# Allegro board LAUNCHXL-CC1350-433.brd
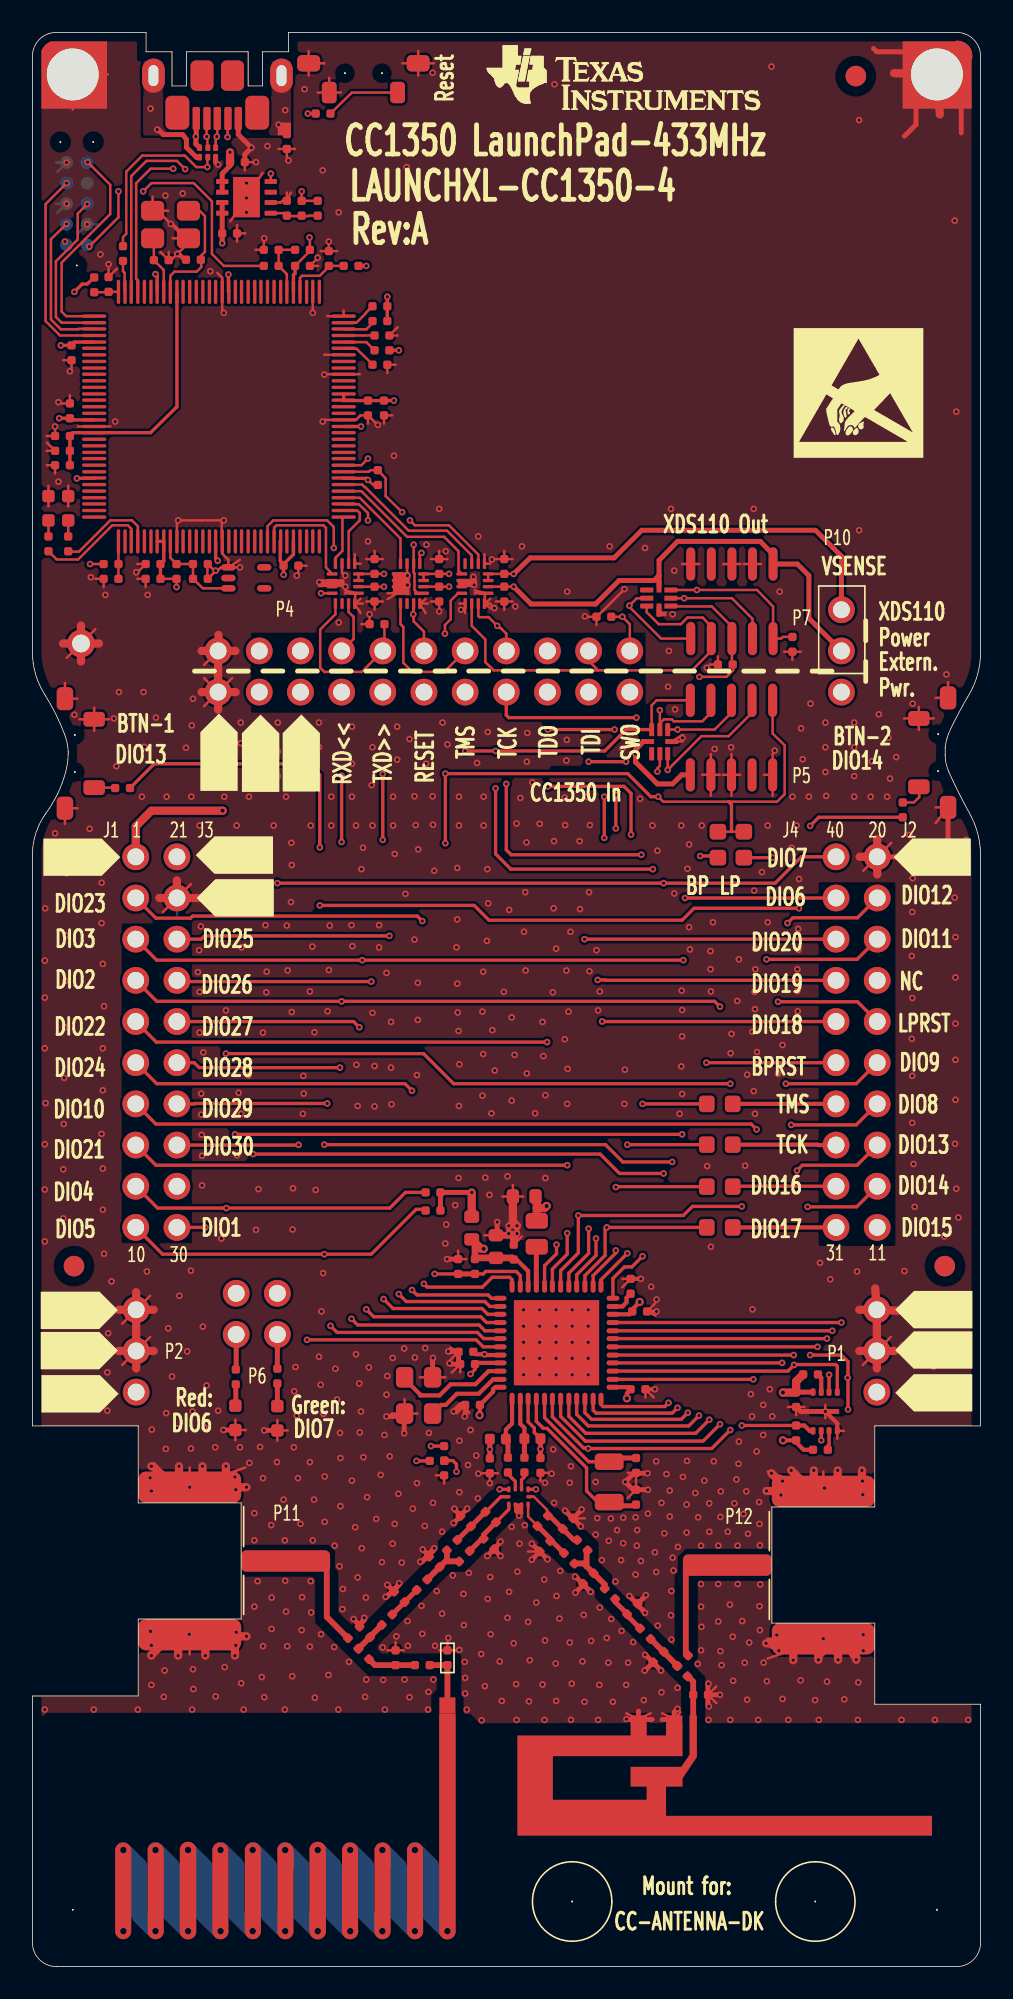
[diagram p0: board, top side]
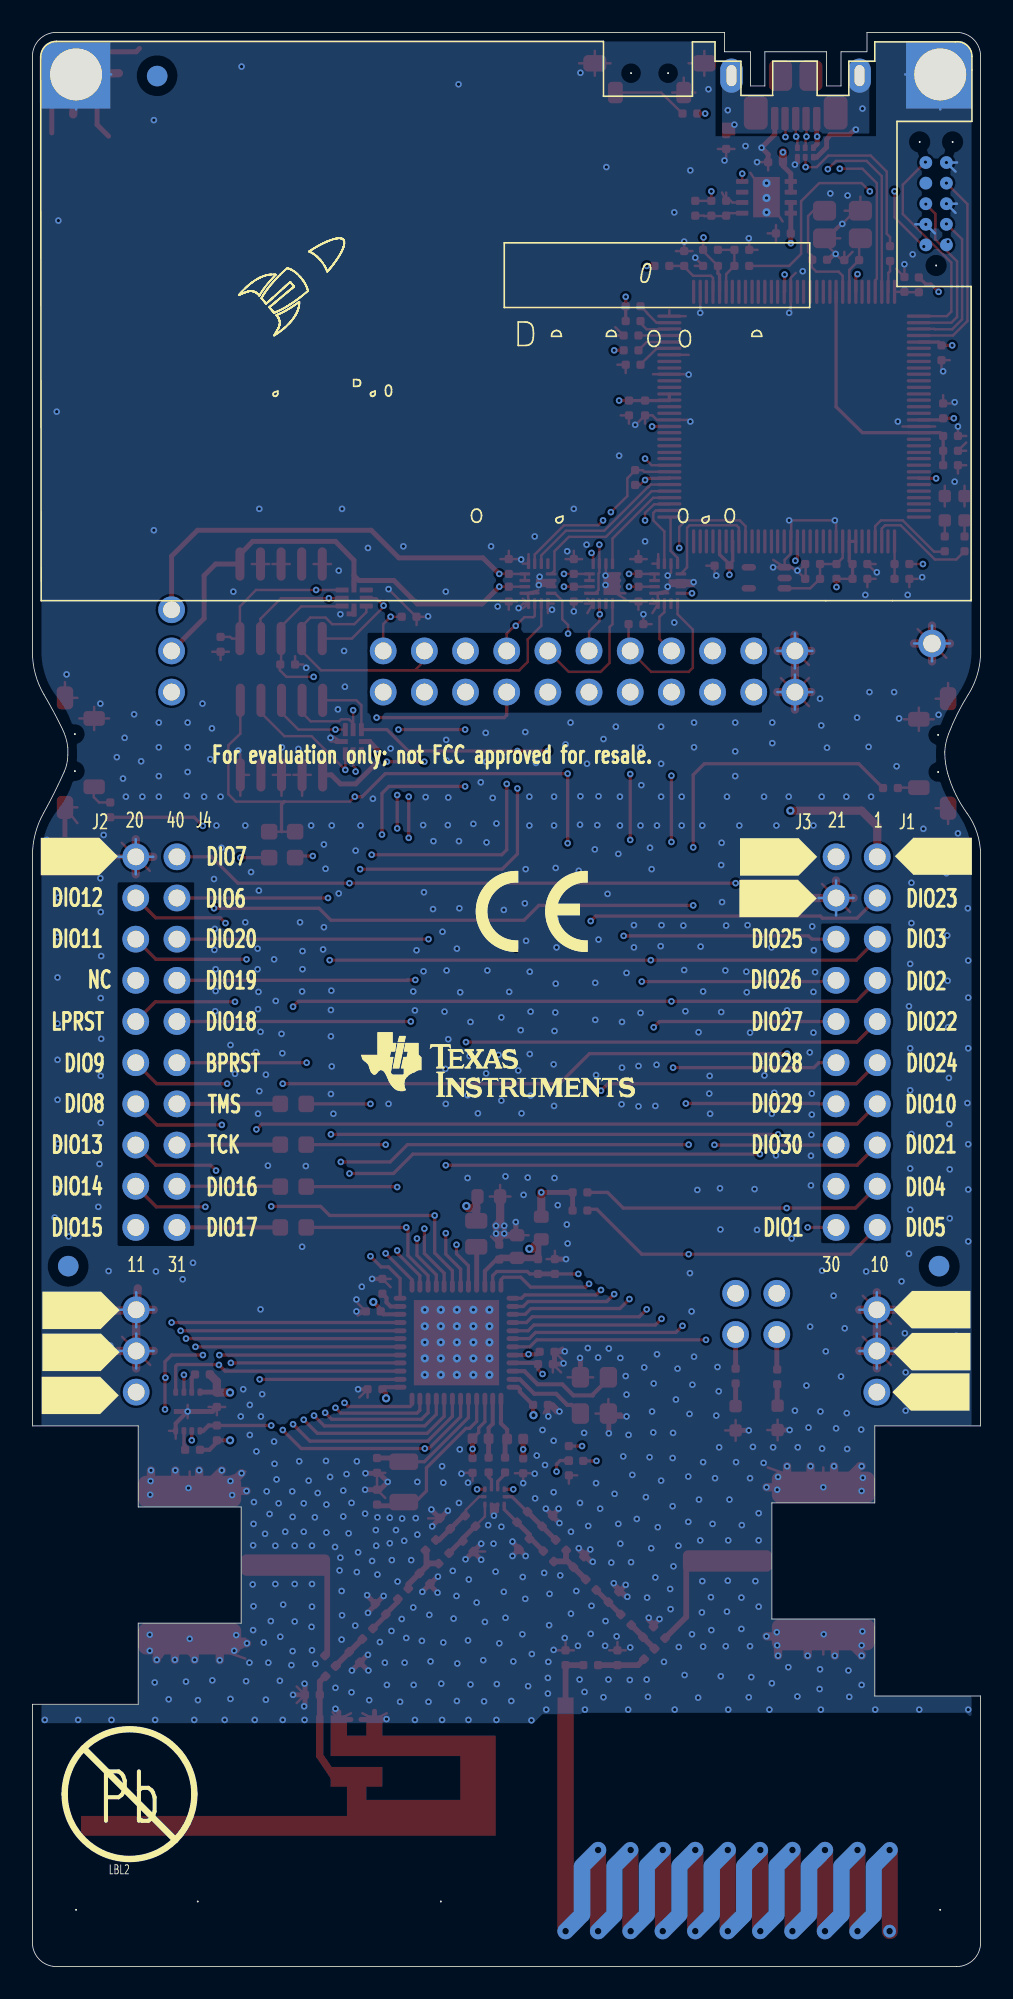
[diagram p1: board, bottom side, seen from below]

Outline 58.5 x 119.3 mm; copper layers: TOP, L2, L3, BOTTOM. Coordinates in mm from the lower left corner of the outline.
Outline path: 0,117.86 0,81.1 arc(0.19,79.73) 0.76,78.46 arc(1.43,77.27) 1.98,76.02 arc(2.14,75.49) 2.21,74.93 2.21,74.85 arc(2.16,74.23) 2.03,73.61 arc(1.55,72.32) 0.84,71.15 arc(0.21,69.92) 0,68.55 0,33.35 6.53,33.35 6.53,28.6 12.88,28.6 12.88,21.44 6.53,21.44 6.53,16.69 0,16.69 0,1.47 arc(0.43,0.43) 1.47,0 57.05,0 arc(58.07,0.44) 58.5,1.47 58.5,16.18 51.97,16.18 51.97,21.18 45.62,21.18 45.62,28.35 51.97,28.35 51.97,33.35 58.5,33.35 58.5,68.5 arc(58.32,69.87) 57.81,71.15 arc(57.15,72.4) 56.54,73.69 arc(56.37,74.19) 56.31,74.73 56.31,75.18 arc(56.43,75.77) 56.64,76.33 arc(57.19,77.41) 57.79,78.46 arc(58.32,79.73) 58.5,81.1 58.5,117.83 arc(58.06,118.87) 57.02,119.3 15.8,119.3 15.8,118.11 14.2,118.11 14.2,116 13.31,116 13.31,118.11 9.5,118.11 9.5,116 8.61,116 8.61,118.11 7.01,118.11 7.01,119.3 1.47,119.3 arc(0.44,118.88) 0,117.86

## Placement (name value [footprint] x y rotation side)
A1  Antenna PCB helix 868/915MHz  [ANTENNA868_915MHZ_A2N]  25.6 16.1 180 top
A2  2.4GHz  [ANTENNA_DN007AN]  40.77 15.24 180 top
C3  100nF  [CAPC1005X60B2N]  36.91 35.61 0 top
C4  100nF  [CAPC1005X60B2N]  37.01 40.41 0 top
C5  100nF  [CAPC1005X60B2N]  27.2 37.92 180 top
C6  22uF  [CAPC1608X100A2L]  28.6 43.71 90 top
C7  100nF  [CAPC1005X60B2N]  29.69 43.61 90 top
C8  22uF  [CAPC1608X100A2L]  31.04 47.5 180 top
C9  100nF  [CAPC1005X60B2N]  27.61 34.65 180 top
C11  8.2pF  [CAPC1005X60B2N]  27.05 27.15 135 top
C12  4.7pF  [CAPC1005X60B2N]  25.12 24.64 135 top
C13  12pF  [CAPC1005X60B2N]  22.96 22.48 135 top
C14  4.7pF  [CAPC1005X60B2N]  20.83 20.32 135 top
C15  330pF  [CAPC1005X60B2N]  20.12 19.61 315 top
C16  100nF  [CAPC1005X60B2N]  27.31 37.16 180 top
C17  12pF  [CAPC1005X60B2N]  37.24 28.5 90 top
C18  12pF  [CAPC1005X60B2N]  37.24 31.37 270 top
C19  1uF  [CAPC1005X60B2N]  36.91 41.5 90 top
C20  100nF  [CAPC1005X60B2N]  26.26 42.72 90 top
C21  1pF  [CAPC1005X60B2N]  31.29 25.6 45 top
C22  8.2pF  [CAPC1005X60B2N]  26.97 25.63 225 top
C24  1.5pF  [CAPC1005X60B2N]  40.41 17.91 135 top
C30  100nF  [CAPC1005X60B2N]  47.12 35.43 270 top
C32  100nF  [CAPC1005X60B2N]  9.91 86.51 0 top
C33  12pF  [CAPC1005X60B2N]  10.39 105.28 180 top
C34  12pF  [CAPC1005X60B2N]  7.49 105.26 0 top
C35  10nF  [CAPC1005X60B2N]  15.49 86.41 0 top
C36  10nF  [CAPC1005X60B2N]  2.31 95.5 90 top
C37  10nF  [CAPC1005X60B2N]  2.41 100 270 top
C38  100nF  [CAPC1005X60B2N]  16.21 104.9 0 top
C39  100nF  [CAPC1005X60B2N]  20.7 96.6 270 top
C40  1uF  [CAPC1005X60B2N]  21.69 96.6 270 top
C41  10nF  [CAPC1005X60B2N]  7.9 86.51 180 top
C42  1uF  [CAPC1005X60B2N]  7.9 85.6 180 top
C43  100nF  [CAPC1005X60B2N]  2.31 94.41 180 top
C44  1uF  [CAPC1005X60B2N]  2.31 93.5 180 top
C45  2.2uF  [CAPC1005X60B2N]  2.31 92.61 180 top
C46  100nF  [CAPC1005X60B2N]  18.29 104.9 90 top
C47  15pF  [CAPC1005X60B2N]  16.61 108.92 270 top
C48  2.2uF  [CAPC1005X60B2N]  12.19 111.3 0 top
C49  2.2uF  [CAPC1005X60B2N]  11.71 106.91 0 top
C50  10nF  [CAPC1005X60B2N]  9.91 85.6 0 top
C52  100nF  [CAPC1005X60B2N]  21.11 85.9 90 top
C53  100nF  [CAPC1005X60B2N]  21.11 85.12 270 top
C54  100nF  [CAPC1005X60B2N]  25.1 85.9 90 top
C55  100nF  [CAPC1005X60B2N]  25.1 85.12 270 top
C56  100nF  [CAPC1005X60B2N]  29.11 85.9 90 top
C57  100nF  [CAPC1005X60B2N]  29.11 85.12 270 top
C58  100pF  [CAPC1005X60B2N]  31.34 31.37 270 top
C59  DNM  [CAPC1005X60B2N]  40.77 16.76 0 top
C60  1pF  [CAPC1005X60B2N]  33.6 26.31 315 top
C61  DNM_0402  [CAPC1005X60B2N]  34.62 24.26 225 top
C62  3.6pF  [CAPC1005X60B2N]  37.34 22.38 225 top
C63  12pF  [CAPC1005X60B2N]  29.34 31.39 270 top
C64  12pF  [CAPC1005X60B2N]  30.35 31.39 270 top
C65  100pF  [CAPC1005X60B2N]  28.22 31.34 270 top
C67  DNM_0402  [CAPC1005X60B2N]  39.8 18.54 45 top
C68  1pF  [CAPC1005X60B2N]  38.3 18.77 45 top
C69  DNM_0402  [CAPC1005X60B2N]  20.12 19.61 135 top
C70  100nF  [CAPC1005X60B2N]  4.7 103.3 90 top
C71  1.8pF  [CAPC1005X60B2N]  23.6 18.59 0 top
CR1  LPL296-J2L2-25  [LEDC1707X65L]  15.11 33.07 90 top
CR2  LS L296-P2Q2-1  [LEDC1708X67L]  12.52 33.1 90 top
CR4  LS L296-P2Q2-1  [LEDC1708X67L]  0.99 90.7 270 top
CR5  LPL296-J2L2-25  [LEDC1707X65L]  2.21 90.7 270 top
CR6  TPD4E004DRY  [SON50P100X145X60-6N]  10.31 111.61 0 top
CR7  TPD6E004RSER  [QFN50P150X150X60-8N]  37.9 84.91 270 top
CR8  TPD6E004RSER  [QFN50P150X150X60-8N]  38.2 74.8 0 top
FIDU1  FIDU_1.27mm  [FID127X142]  50.8 116.61 0 top
FIDU2  FIDU_1.27mm  [FID127X142]  2.57 43.21 0 top
FIDU3  FIDU_1.27mm  [FID127X142]  56.29 43.21 0 top
FIDU4  FIDU_1.27mm  [FID127X142]  50.8 116.61 180 bottom
FIDU5  FIDU_1.27mm  [FID127X142]  2.57 43.21 180 bottom
FIDU6  FIDU_1.27mm  [FID127X142]  56.29 43.21 180 bottom
FL1  BLM18HE152SN1  [FIL_BLM18HE152SN1DL]  27.1 44.86 90 top
J1  SSQ-110-23-L-D  [SAMTEC_SSQ11023LD_A2B]  6.38 68.45 0 bottom
J2  SSQ-110-23-L-D  [SAMTEC_SSQ11023LD_A2B]  49.58 68.45 0 bottom
J6  105164-0001  [MOLEX_1051640001_A2N]  10.11 114 0 top
L1  6.8uH  [INDC2012X150L]  31.12 44.4 90 top
L11  2.2nH  [INDC1005X60B2N]  32.72 27 45 top
L12  15nH  [INDC1005X60B2N]  26.21 26.31 225 top
L13  20nH  [INDC1005X60B2N]  24.36 23.88 225 top
L14  20nH  [INDC1005X60B2N]  22.2 21.72 225 top
L21  2.2nH  [INDC1005X60B2N]  32.79 25.5 315 top
L25  1.5nH  [INDC1005X60B2N]  35.31 23.32 315 top
L26  2.2nH  [INDC1005X60B2N]  37.49 20.85 315 top
L27  15nH  [INDC1005X60B2N]  27.84 26.39 315 top
L28  100nH  [IND_LQW15AN]  29.21 32.54 180 top
L29  100nH  [IND_LQW15AN]  30.35 32.56 0 top
L30  33nH  [INDC1005X60B2N]  28.6 27.41 135 top
L31  DNM  [INDC1005X60B2N]  31.8 27.81 225 top
L32  DNM  [INDC1005X60B2N]  22.4 18.59 90 top
L33  33nH  [INDC1005X60B2N]  25.6 18.59 90 top
LBL2  NON_COMPONENT_LABEL_8mm  [LABEL_PB-FREE_8MM_A2N]  56.72 6.43 180 bottom
LBL4  CE_label  [CE_LABEL]  28.52 62.59 180 bottom
M1  SNT-100-BK-G  [SAMTEC_SNT100BKG]  12.7 77.39 90 top
M2  SNT-100-BK-G  [SAMTEC_SNT100BKG]  15.29 77.39 90 top
M3  SNT-100-BK-G  [SAMTEC_SNT100BKG]  17.81 77.39 90 top
M4  SNT-100-BK-G  [SAMTEC_SNT100BKG]  20.29 77.39 90 top
M5  SNT-100-BK-G  [SAMTEC_SNT100BKG]  22.91 77.39 90 top
M6  SNT-100-BK-G  [SAMTEC_SNT100BKG]  25.4 77.39 90 top
M7  SNT-100-BK-G  [SAMTEC_SNT100BKG]  27.99 77.39 90 top
M8  SNT-100-BK-G  [SAMTEC_SNT100BKG]  30.51 77.39 90 top
M9  SNT-100-BK-G  [SAMTEC_SNT100BKG]  33.1 77.39 90 top
M10  SNT-100-BK-G  [SAMTEC_SNT100BKG]  35.61 77.39 90 top
M11  SNT-100-BK-G  [SAMTEC_SNT100BKG]  38.1 77.39 90 top
M12  SNT-100-BK-G  [SAMTEC_SNT100BKG]  51.21 79.91 90 top
M13  SNT-100-BK-G  [SAMTEC_SNT100BKG]  13.77 37.69 90 top
M14  SNT-100-BK-G  [SAMTEC_SNT100BKG]  16.38 37.69 90 top
MH1  HOLE_3.2mm_NPL  [MTG320]  2.49 3.51 0 top
MH2  HOLE_3.2mm_NPL  [MTG320]  55.8 3.51 0 top
MH3  HOLE_3.2mm_PTH  [MTG320_380]  2.49 116.71 0 top
MH4  HOLE_3.2mm_PTH  [MTG320_380]  55.8 116.71 0 top
MH5  HOLE_1.1mm_PTH  [MTG110_170]  3 81.61 0 top
NOREF  -  []  8.41 66.01 0 top
NOREF#2  -  []  0.61 67.21 0 top
NOREF#3  -  []  51.51 38.1 0 top
NOREF#4  -  []  0 117.65 0 top
NOREF#5  -  []  53.81 0 90 top
NOREF#6  -  []  51.51 35.61 0 top
NOREF#7  #VALUE  [unnamed#2]  33.3 4.01 0 top
NOREF#8  -  []  1.47 0 90 top
NOREF#9  -  []  13.89 70.21 90 top
NOREF#10  -  []  55.6 0 90 top
NOREF#11  -  []  51.41 66.01 0 top
NOREF#12  -  []  0 1.75 0 top
NOREF#13  -  []  8.41 63.5 0 top
NOREF#14  -  []  56.54 0 90 top
NOREF#15  -  []  1.47 0 90 top
NOREF#16  -  []  53.01 34.01 0 top
NOREF#17  #VALUE  []  46.96 93.07 0 top
NOREF#18  -  []  -1.9 32.79 0 top
NOREF#19  -  []  17.81 72.42 90 top
NOREF#20  -  []  78.99 112.19 0 top
NOREF#21  -  []  16.61 70 90 top
NOREF#22  -  []  -1.8 35.61 0 top
NOREF#23  -  []  -1.8 38.1 0 top
NOREF#24  -  []  0 117.86 0 top
NOREF#25  -  []  7.11 38.1 180 bottom
NOREF#26  -  []  57.99 34.01 180 bottom
NOREF#27  -  []  60.2 35.51 180 bottom
NOREF#28  -  []  17.2 63.5 180 bottom
NOREF#29  -  []  60.3 66.09 180 bottom
NOREF#30  -  []  17.3 65.91 180 bottom
NOREF#31  -  []  60.2 38.1 180 bottom
NOREF#32  -  []  7.11 35.51 180 bottom
NOREF#33  -  []  51.54 89.54 180 bottom
NOREF#34  -  []  5.51 67.11 180 bottom
NOREF#35  -  []  7.11 32.89 180 bottom
P1  BB02-HC031-KB1-603000  [GRADCONN_BB02HC031KB1603000_A2B]  52.1 35.43 90 top
P2  BB02-HC031-KB1-603000  [GRADCONN_BB02HC031KB1603000_A2B]  6.4 35.43 90 top
P4  BB02-HJ221-KB1-603000  [GRADCONN_BB02HJ221KB160300_A2B]  36.86 81.15 180 top
P5  FTSH-105-01-F-DV-K  [SAMTEC_FTSH-105-01-F-DV-K-10L]  40.59 73.51 0 top
P6  BB02-HJ041-KB1-603000  [GRADCONN_BB02HJ041KB1603000_A2B]  12.57 38.99 0 top
P7  FTSH-105-01-F-DV-K  [SAMTEC_FTSH-105-01-F-DV-K-10L]  45.69 86.51 180 top
P8  TC2050-IDC-NL  [TAGCONNECT_TC2050IDCNLN]  2.11 106.2 90 bottom
P10  BB02-HC031-KB1-603000  [GRADCONN_BB02HC031KB1603000_A2B]  49.91 83.69 270 top
P11  142-0721-88  [CINCH_1420721882_A2N]  15.62 25.02 180 top
P12  142-0721-88  [CINCH_1420721882_A2N]  42.88 24.76 0 top
R1  100k  [RESC1005X40B2N]  27.31 42.72 90 top
R2  3.3k  [RESC1005X40B2N]  24.26 47.75 0 top
R3  3.3k  [RESC1005X40B2N]  24.26 46.63 0 top
R11  2.2k  [RESC1005X40B2N]  47.12 33.38 270 top
R14  220  [RESC1005X40B2N]  12.55 35.92 90 top
R15  180  [RESC1005X40B2N]  15.11 35.97 90 top
R17  10k  [RESC1005X40B2N]  16.21 105.89 0 top
R18  4.7k  [RESC1005X40B2N]  8.89 86.51 270 top
R19  DNM  [RESC1005X40B2N]  5.59 105.21 90 top
R20  100  [RESC1005X40B2N]  15.19 104.9 180 top
R21  DNM  [RESC1005X40B2N]  15.19 105.89 180 top
R22  330k  [RESC1005X40B2N]  5.31 86.51 180 top
R23  180  [RESC1005X40B2N]  0.99 88.21 270 top
R24  220k  [RESC1005X40B2N]  5.31 85.6 180 top
R25  220  [RESC1005X40B2N]  2.21 88.21 270 top
R27  1k  [RESC1005X40B2N]  21.89 101.5 180 top
R28  4.87k  [RESC1005X40B2N]  21.89 98.81 180 top
R29  1k  [RESC1005X40B2N]  21.11 100.61 0 top
R30  1k  [RESC1005X40B2N]  21.11 99.69 0 top
R31  51  [RESC1005X40B2N]  19.2 104.9 0 top
R32  33k  [RESC1005X40B2N]  15.7 112.12 90 top
R33  51k  [RESC1005X40B2N]  17.6 108 90 top
R34  30k  [RESC1005X40B2N]  15.7 108.92 270 top
R39  1k  [RESC1005X40B2N]  21.89 102.41 180 top
R46  DNM  [RESC1608X55N]  43.21 53.21 180 top
R47  DNM  [RESC1608X55N]  43.21 50.7 180 top
R48  DNM  [RESC1608X55N]  43.21 48.11 180 top
R49  DNM  [RESC1608X55N]  43.21 45.59 180 top
R51  DNM  [RESC1608X55N]  43.89 68.4 90 top
R52  0  [RESC1608X55N]  42.29 70 270 top
R55  100  [RESC1005X40B2N]  53.7 71.81 270 top
R56  100  [RESC1005X40B2N]  5.11 72.69 0 top
R57  100  [RESC1005X40B2N]  18.39 114.3 180 top
R58  3.3k  [RESC1005X40B2N]  21.31 92.3 270 top
R59  DNM  [RESC1005X40B2N]  49.07 31.88 180 top
R60  DNM  [RESC1005X40B2N]  48.46 36.53 180 top
R61  100k  [RESC1005X40B2N]  20.8 82.8 0 top
R62  100k  [RESC1005X40B2N]  34.8 83.26 0 top
R63  100k  [RESC1005X40B2N]  42.29 80.31 0 top
R65  100k  [RESC1005X40B2N]  46.89 81.1 90 top
R66  100  [RESC1005X40B2N]  3.81 104.19 270 top
R67  DNM  [RESC1005X40B2N]  24.51 31.19 0 top
R68  DNM  [RESC1005X40B2N]  25.4 30.3 90 top
R69  0  [RESC1005X40B2N]  25.4 31.19 90 top
SW1  1188E-1K2-V  [SW_1188E1K2V_A2N]  2.01 78.21 270 top
SW2  1188E-1K2-V  [SW_1188E1K2V_A2N]  56.49 71.5 90 top
SW3  1188E-1K2-V  [SW_1188E1K2V_A2N]  23.8 117.4 180 top
U1  CC1350F128RGZ  [QFNFC50P700X700X80-49CN]  29.59 35 0 top
U4  MX25R8035FZUIL0  [SON50P300X200X60-9B2L]  48.16 33.05 0 top
U5  TM4C1294NCPDTT3R  [QFP40P1600X1600X120-128N]  5.31 87.91 0 top
U6  LM4040B25IDCK  [SOT65P210X110-5N]  12.09 86.31 270 top
U7  TPS79601DR  [SON65P300X300X100-9AL]  11.71 110.11 270 top
U8  SN74AVC4T245RSV  [QFNFC40P180X260X55-16A2L]  19.99 84.71 90 top
U9  SN74AVC4T245RSV  [QFNFC40P180X260X55-16A2L]  27.99 84.71 90 top
U10  SN74AVC4T245RSV  [QFNFC40P180X260X55-16A2L]  24 84.71 90 top
U11  XMSSJE3G0PA-003  [SW_XMSSJE3G0PA003_A2N]  29.39 28.5 0 top
UNK#REFDES  -  []  29.01 118.52 0 top
UNK#REFDES#2  -  []  37.21 57.63 180 bottom
Y1  32.768kHz  [XTAL_FC-135N]  35.59 28.65 90 top
Y2  24MHz  [OSCCC250X320X60-4L]  24.69 34.11 90 top
Y3  16MHz  [OSCCC250X320X100-4BN]  9.63 108.31 180 top

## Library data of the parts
A1 = ANTENNA_0: User Part Number: #PN
A2 = ANTENNA_DN007_0
C3-C5 C7 C9 C11-C22 C24 C30 C32-C50 C52-C65 C67-C71 = CAPACITOR: User Part Number: #PN
C6 C8 = CAPACITOR: User Part Number: #PN; alternate symbols: (CAPC1608X100A2L,CAPC1608X100A2M)
CR1 CR5 = LED: alternate symbols: (LEDC1707X65L,LEDC1707X65M)
CR2 CR4 = LED: alternate symbols: (LEDC1708X67L,LEDC1708X67M)
CR6 = DIODE_TPD4E004_SON6: User Part Number: #PN; alternate symbols: (SON50P100X145X65-6L,SON50P100X145X65-6M)
CR7 CR8 = DIODE_TVS_TPD6E004_QFN8: alternate symbols: (QFN50P150X150X60-8L,QFN50P150X150X60-8M)
FIDU1-FIDU6 = FIDMARK
FL1 = FILTER_0: alternate symbols: (FIL_BLM18HE152SN1DL,FIL_BLM18HE152SN1DM)
J1 J2 = CONN_HEADER_2X10_J_S_V1: User Part Number: #PN; alternate symbols: (SAMTEC_SSQ11023LD_A2C,SAMTEC_SSQ11023LD_A2A)
J6 = CONN_USB_MICRO_B_2MH: User Part Number: #PN; alternate symbols: (MOLEX_1051640001_A2L,MOLEX_1051640001_A2M)
L1 = INDUCTOR_0: alternate symbols: (INDC2012X150L,INDC2012X150M)
L11-L14 L21 L25-L27 L30-L32 = INDUCTOR_0: User Part Number: #PN
L28 L29 = INDUCTOR_0: alternate symbols: (IND_LQW15AM,IND_LQW15AL)
L33 = INDUCTOR: User Part Number: #PN
LBL2 = LABEL_Pb-free_V1: User Part Number: #PN
LBL4 = CE_LABEL
M1-M14 = MECH_SHUNT_JUMPER_V1: User Part Number: #PN
MH1 MH2 = HOLE_NPL
MH3-MH5 = HOLE_PTH
NOREF#7 NOREF#17 = -: User Part Number: #PN
P1 P2 P10 = CONN_HEADER_3_P_S: User Part Number: #PN; alternate symbols: (GRADCONN_BB02HC031KB1603000_A2C,GRADCONN_BB02HC031KB1603000_A2A)
P4 = CONN_HEADER_2X11_P_S: User Part Number: #PN; alternate symbols: (GRADCONN_BB02HJ221KB160300_A2C,GRADCONN_BB02HJ221KB160300_A2A)
P5 P7 = CONN_HEADER_2X5: alternate symbols: (SAMTEC_FTSH-105-01-F-DV-K-10L,SAMTEC_FTSH-105-01-F-DV-K-10M)
P6 = CONN_HEADER_2X2_P: User Part Number: #PN; alternate symbols: (GRADCONN_BB02HJ041KB1603000_A2C,GRADCONN_BB02HJ041KB1603000_A2A)
P8 = CONN_IDC_TC2050-IDC-NL: User Part Number: #PN; alternate symbols: (TAGCONNECT_TC2050IDCNLL,TAGCONNECT_TC2050IDCNLM)
P11 = CONN_COAX_1_J_4: User Part Number: #PN
P12 = CONN_COAX_1_J_1: User Part Number: #PN
R1-R3 R11 R14 R15 R17-R25 R27-R34 R39 R55-R63 R65-R69 = RESISTOR: User Part Number: #PN
R46-R49 R51 R52 = RESISTOR: alternate symbols: (RESC1608X55L,RESC1608X55M)
SW1-SW3 = SWITCH_TACT_V2: alternate symbols: (SW_1188E1K2V_A2L,SW_1188E1K2V_A2M)
U1 = IC_RF_CC13XX_7X7_QFN48_V2: alternate symbols: (QFNFC50P700X700X80-49CL,QFNFC50P700X700X80-49CM)
U4 = IC_FLASH_MX25R8035F_USON8: User Part Number: #PN; alternate symbols: (SON50P300X200X60-9B2L,SON50P300X200X60-9B2M)
U5 = IC_PROC_TM4C1294NCPDT_TQFP128: alternate symbols: (QFP40P1600X1600X120-128L,QFP40P1600X1600X120-128M)
U6 = IC_REF_LM4040_SC70-5: alternate symbols: (SOT65P210X110-5L,SOT65P210X110-5M)
U7 = IC_PM_TPS79601_SON8: alternate symbols: (SON65P300X300X100-9AL,SON65P300X300X100-9AM)
U8-U10 = IC_XCVR_SN74AVC4T245_UQFN16_2: User Part Number: #PN; alternate symbols: (QFNFC40P180X260X55-16A2L,QFNFC40P180X260X55-16A2M)
U11 = IC_SWITCH_XMSSJE3G0PA-00: User Part Number: #PN
Y1 = CRYSTAL: alternate symbols: (XTAL_FC-135L,XTAL_FC-135M)
Y2 = XTAL_4PIN_S: alternate symbols: (OSCCC250X320X60-4L,OSCCC250X320X60-4M)
Y3 = XTAL_4: alternate symbols: (OSCCC250X320X100-4BL,OSCCC250X320X100-4BM)

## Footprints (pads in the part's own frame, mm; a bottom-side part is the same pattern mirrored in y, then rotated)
ANTENNA868_915MHZ_A2N
  rect 0.991x0.991 smd: 1(0,0)
ANTENNA_DN007AN
  rect 0.457x0.508 smd: 1(0,0)
  rect 0.991x0.508 smd: 2(1.168,0) 3(3.378,0)
CAPC1005X60B2N
  custom 0.127x0.127 smd: 1(0,0) 2(0.914,0)
CAPC1608X100A2L
  custom 0.191x0.191 smd: 1(0,0) 2(1.397,0)
CE_LABEL
  oval 0.025x0.051 smd: 1(-0.15,0.099)
CINCH_1420721882_A2N
  custom 0.33x0.33 smd: 1(0,0)
  custom 0.483x0.483 smd: M1(5.918,-4.547) M2(5.918,4.547)
FID127X142
  round 1.27 smd: 1(0,0)
FIL_BLM18HE152SN1DL
  custom 0.191x0.191 smd: 1(0,0) 2(1.397,0)
GRADCONN_BB02HC031KB1603000_A2B
  round 1.651 hole 1.041: 1(0,0) 2(2.54,0) 3(5.08,0)
GRADCONN_BB02HJ041KB1603000_A2B
  round 1.651 hole 1.041: 1(0,0) 2(0,2.54) 3(2.54,0) 4(2.54,2.54)
GRADCONN_BB02HJ221KB160300_A2B
  round 1.651 hole 1.041: 1(0,0) 2(0,2.54) 3(2.54,0) 4(2.54,2.54) 5(5.08,0) 6(5.08,2.54) 7(7.62,0) 8(7.62,2.54) 9(10.16,0) 10(10.16,2.54) 11(12.7,0) 12(12.7,2.54) 13(15.24,0) 14(15.24,2.54) 15(17.78,0) 16(17.78,2.54) 17(20.32,0) 18(20.32,2.54) 19(22.86,0) 20(22.86,2.54) 21(25.4,0) 22(25.4,2.54)
IND_LQW15AN
  custom 0.152x0.152 smd: 1(0,0) 2(0.991,0)
INDC1005X60B2N
  custom 0.127x0.127 smd: 1(0,0) 2(0.914,0)
INDC2012X150L
  custom 0.242x0.242 smd: 1(0,0) 2(1.6,0)
LEDC1707X65L
  custom 0.191x0.191 smd: 1(0,0) 2(1.499,0)
LEDC1708X67L
  custom 0.191x0.191 smd: 1(0,0) 2(1.499,0)
MOLEX_1051640001_A2N
  custom 0.368x0.368 smd: (-1.168,0.356) (3.759,0.356)
  custom 0.356x0.356 smd: (0.356,2.642) (2.235,2.642)
  custom 0.115x0.115 smd: 1(0,0) 2(0.66,0) 3(1.295,0) 4(1.956,0) 5(2.591,0)
  oval 1.397x2.108 hole 0.61x1.295: M1(-2.642,2.642) M2(5.258,2.642)
MTG110_170
  round 1.702 hole 1.092: 1(0,0)
MTG320
  round 0.102 hole 3.2 unplated: (0,0)
MTG320_380
  round 3.81 hole 3.2: 1(0,0)
OSCCC250X320X60-4L
  custom 0.267x0.267 smd: 1(0,0) 2(2.235,0) 3(2.235,1.727) 4(0,1.727)
OSCCC250X320X100-4BN
  custom 0.305x0.305 smd: 1(0,0) 2(2.21,0) 3(2.21,1.702) 4(0,1.702)
QFN50P150X150X60-8N
  custom 0.076x0.076 smd: 1(0,0) 2(0.508,0) 3(0.991,0) 4(1.245,0.762) 5(0.991,1.499) 6(0.508,1.499) 7(0,1.499) 8(-0.254,0.762)
QFNFC40P180X260X55-16A2L
  custom 0.051x0.051 smd: 1(0,0) 2(0.406,-0.127) 3(0.787,-0.127) 4(1.194,-0.127) 5(1.829,0.102) 6(1.829,0.483) 7(1.829,0.889) 8(1.829,1.295) 9(1.194,1.499) 10(0.787,1.499) 11(0.406,1.499) 12(0,1.499) 13(-0.635,1.295) 14(-0.635,0.889) 15(-0.635,0.483) 16(-0.635,0.102)
QFNFC50P700X700X80-49CN
  oval 0.305x0.787 smd: 1(0,0) 2(0.508,0) 3(0.991,0) 4(1.499,0) 5(2.007,0) 6(2.489,0) 7(2.997,0) 8(3.505,0) 9(3.988,0) 10(4.496,0) 11(5.004,0) 12(5.486,0) 25(5.486,6.96) 26(5.004,6.96) 27(4.496,6.96) 28(3.988,6.96) 29(3.505,6.96) 30(2.997,6.96) 31(2.489,6.96) 32(2.007,6.96) 33(1.499,6.96) 34(0.991,6.96) 35(0.508,6.96) 36(0,6.96)
  oval 0.787x0.305 smd: 13(6.223,0.737) 14(6.223,1.219) 15(6.223,1.727) 16(6.223,2.235) 17(6.223,2.718) 18(6.223,3.226) 19(6.223,3.734) 20(6.223,4.216) 21(6.223,4.724) 22(6.223,5.232) 23(6.223,5.715) 24(6.223,6.223) 37(-0.737,6.223) 38(-0.737,5.715) 39(-0.737,5.232) 40(-0.737,4.724) 41(-0.737,4.216) 42(-0.737,3.734) 43(-0.737,3.226) 44(-0.737,2.718) 45(-0.737,2.235) 46(-0.737,1.727) 47(-0.737,1.219) 48(-0.737,0.737)
  rect 5.258x5.258 smd: 49(2.743,3.48)
QFP40P1600X1600X120-128N
  oval 0.203x1.499 smd: 1(0,0) 2(0.406,0) 3(0.787,0) 4(1.194,0) 5(1.6,0) 6(2.007,0) 7(2.388,0) 8(2.794,0) 9(3.2,0) 10(3.607,0) 11(3.988,0) 12(4.394,0) 13(4.801,0) 14(5.207,0) 15(5.613,0) 16(5.994,0) 17(6.401,0) 18(6.807,0) 19(7.214,0) 20(7.595,0) 21(8.001,0) 22(8.407,0) 23(8.788,0) 24(9.195,0) 25(9.601,0) 26(10.008,0) 27(10.389,0) 28(10.795,0) 29(11.201,0) 30(11.608,0) 31(11.989,0) 32(12.395,0) 65(12.395,15.392) 66(11.989,15.392) 67(11.608,15.392) 68(11.201,15.392) 69(10.795,15.392) 70(10.389,15.392) 71(10.008,15.392) 72(9.601,15.392) 73(9.195,15.392) 74(8.788,15.392) 75(8.407,15.392) 76(8.001,15.392) 77(7.595,15.392) 78(7.214,15.392) 79(6.807,15.392) 80(6.401,15.392) 81(5.994,15.392) 82(5.613,15.392) 83(5.207,15.392) 84(4.801,15.392) 85(4.394,15.392) 86(3.988,15.392) 87(3.607,15.392) 88(3.2,15.392) 89(2.794,15.392) 90(2.388,15.392) 91(2.007,15.392) 92(1.6,15.392) 93(1.194,15.392) 94(0.787,15.392) 95(0.406,15.392) 96(0,15.392)
  oval 1.499x0.203 smd: 33(13.894,1.499) 34(13.894,1.905) 35(13.894,2.311) 36(13.894,2.692) 37(13.894,3.099) 38(13.894,3.505) 39(13.894,3.912) 40(13.894,4.293) 41(13.894,4.699) 42(13.894,5.105) 43(13.894,5.486) 44(13.894,5.893) 45(13.894,6.299) 46(13.894,6.706) 47(13.894,7.087) 48(13.894,7.493) 49(13.894,7.899) 50(13.894,8.306) 51(13.894,8.712) 52(13.894,9.093) 53(13.894,9.5) 54(13.894,9.906) 55(13.894,10.312) 56(13.894,10.693) 57(13.894,11.1) 58(13.894,11.506) 59(13.894,11.913) 60(13.894,12.294) 61(13.894,12.7) 62(13.894,13.106) 63(13.894,13.487) 64(13.894,13.894) 97(-1.499,13.894) 98(-1.499,13.487) 99(-1.499,13.106) 100(-1.499,12.7) 101(-1.499,12.294) 102(-1.499,11.913) 103(-1.499,11.506) 104(-1.499,11.1) 105(-1.499,10.693) 106(-1.499,10.312) 107(-1.499,9.906) 108(-1.499,9.5) 109(-1.499,9.093) 110(-1.499,8.712) 111(-1.499,8.306) 112(-1.499,7.899) 113(-1.499,7.493) 114(-1.499,7.087) 115(-1.499,6.706) 116(-1.499,6.299) 117(-1.499,5.893) 118(-1.499,5.486) 119(-1.499,5.105) 120(-1.499,4.699) 121(-1.499,4.293) 122(-1.499,3.912) 123(-1.499,3.505) 124(-1.499,3.099) 125(-1.499,2.692) 126(-1.499,2.311) 127(-1.499,1.905) 128(-1.499,1.499)
RESC1005X40B2N
  custom 0.127x0.127 smd: 1(0,0) 2(0.914,0)
RESC1608X55N
  custom 0.241x0.241 smd: 1(0,0) 2(1.6,0)
SAMTEC_FTSH-105-01-F-DV-K-10L
  oval 0.559x2.057 smd: 1(0,0) 2(0,4.597) 3(1.27,0) 4(1.27,4.597) 5(2.54,0) 6(2.54,4.597) 7(3.81,0) 8(3.81,4.597) 9(5.08,0) 10(5.08,4.597)
SAMTEC_SSQ11023LD_A2B
  round 1.651 hole 1.041: 1(0,0) 2(2.54,0) 3(0,2.54) 4(2.54,2.54) 5(0,5.08) 6(2.54,5.08) 7(0,7.62) 8(2.54,7.62) 9(0,10.16) 10(2.54,10.16) 11(0,12.7) 12(2.54,12.7) 13(0,15.24) 14(2.54,15.24) 15(0,17.78) 16(2.54,17.78) 17(0,20.32) 18(2.54,20.32) 19(0,22.86) 20(2.54,22.86)
SON50P100X145X60-6N
  custom 0.076x0.076 smd: 1(0,0) 2(0.508,0) 3(0.991,0) 4(0.991,0.584) 5(0.508,0.584) 6(0,0.584)
SON50P300X200X60-9B2L
  custom 0.076x0.076 smd: 1(0,0) 2(0.508,0) 3(0.991,0) 4(1.499,0) 5(1.499,2.388) 6(0.991,2.388) 7(0.508,2.388) 8(0,2.388)
  rect 1.702x0.305 smd: 9(0.762,1.194)
SON65P300X300X100-9AL
  custom 0.077x0.077 smd: 1(0,0) 2(0.66,0) 3(1.295,0) 4(1.956,0) 5(1.956,2.997) 6(1.295,2.997) 7(0.66,2.997) 8(0,2.997)
  rect 2.489x1.651 smd: 9(0.965,1.499)
SOT65P210X110-5N
  oval 0.406x0.889 smd: 1(0,0) 2(0.66,0) 3(1.295,0) 4(1.295,2.21) 5(0,2.21)
SW_1188E1K2V_A2N
  round 0.102 hole 0.889 unplated: (2.235,0.61) (4.521,0.61)
  custom 0.254x0.254 smd: 1(0,0) 2(6.756,0)
  custom 0.229x0.229 smd: 3(1.27,1.803) 4(5.486,1.803)
SW_XMSSJE3G0PA003_A2N
  custom 0.051x0.051 smd: 1(0,0) 2(0.406,-0.025) 3(0.787,-0.025) 4(1.194,0) 5(1.27,0.483) 6(1.194,0.94) 7(0.787,0.965) 8(0.406,0.965) 9(0,0.94) 10(-0.076,0.483)
TAGCONNECT_TC2050IDCNLN
  round 0.102 hole 0.991 unplated: (-1.27,0.635) (6.35,-0.381) (6.35,1.651)
  round 0.787 smd: 1(0,0) 2(1.27,0) 3(2.54,0) 4(3.81,0) 5(5.08,0) 6(5.08,1.27) 7(3.81,1.27) 8(2.54,1.27) 9(1.27,1.27) 10(0,1.27)
unnamed#2
  round 0.102 hole 3.2 unplated: (0,0) (15.001,0)
XTAL_FC-135N
  custom 0.254x0.254 smd: 1(0,0) 2(2.489,0)

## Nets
+5V: J1.2 P2.1 P4.20
GND: A2.2(GND_2) A2.3(GND_3) C3.2 C4.2 C5.2 C6.2 C7.2 C8.2 C9.2 C11.2 C12.2 C13.2 C14.2 C16.2 C17.2 C18.2 C19.2 C20.2 C21.1 C30.2 C32.2 C33.2 C34.2 C35.2 C36.2 C37.2 C38.2 C39.2 C40.2 C41.2 C42.2 C43.2 C44.2 C45.2 C46.2 C48.2 C49.2 C50.2 C52.2 C53.2 C54.2 C55.2 C56.2 C57.2 C58.2 C59.2 C61.2 C62.1 C65.2 C68.1 C70.2 CR1.1(C) CR2.1(C) CR4.1(C) CR5.1(C) CR6.3 CR7.4(GND) CR8.4(GND) J1.4 J2.2 J6.5(GND) L11.2 L27.2 L32.2 L33.2 MH3.1 MH4.1 MH5.1 P1.2 P1.3 P2.2 P2.3 P4.21 P4.22 P5.3 P5.5 P5.9 P7.3 P7.5 P7.9 P8.3(7) P8.5(8) P8.9(10) P11.M1 P11.M2 P12.M1 P12.M2 R21.2 R24.2 R28.1 R29.2 R32.1 R34.1 R61.1 R62.1 R63.1 R65.1 R68.1 SW1.1 SW1.2 SW1.3 SW2.1 SW2.2 SW2.4 SW3.1 SW3.2 SW3.4 U1.49(VSS) U4.4(GND) U4.9(EGP) U5.10(GNDA) U5.17(GND#17) U5.48(GND#48) U5.55(GND#55) U5.58(GND#58) U5.64(NWAKE) U5.66(XOSC0) U5.80(GND#80) U5.114(GND#114) U6.1(ANODE) U7.6(GND) U7.9(GND/TAB) U8.1(1NOE) U8.5(2DIR) U8.7(1A2) U8.10(GND#10) U8.11(GND#11) U8.16(2NOE) U9.1(1NOE) U9.5(2DIR) U9.10(GND#10) U9.11(GND#11) U9.13(2B1) U9.16(2NOE) U10.7(1A2) U10.9(2A2) U10.10(GND#10) U10.11(GND#11) U10.12(2B2) U10.16(2NOE) U11.2(GND#2) U11.3(GND#3) Y2.2 Y2.4 Y3.2(GND) Y3.4(NC_4)
VDDC: C43.1 C44.1 C45.1 U5.87(VDDC#87) U5.115(VDDC#115)
VDDR: C8.1 C9.1 C16.1 L1.2 U1.45(VDDR#45) U1.48(VDDR#48)
VDDS: C3.1 C4.1 C5.1 C6.1 C7.1 FL1.1 R1.2 R67.1 U1.13(VDDS2) U1.22(VDDS3) U1.34(VDDS_DCDC) U1.44(VDDS)
CC1350_RESET: C20.1 CR8.2(IO2) P4.12 P5.10 R1.1 R51.2 R52.1 U1.35(RESET_N)
CC1350_RXD: J1.7 P4.16 U1.7(DIO_2)
CC1350_SW_PWR: J1.16 R69.2 U1.43(DIO_30)
CC1350_SWO: J2.9 P4.2 U1.28(DIO_18)
CC1350_TCK: CR8.6(IO5) P4.8 P5.4 R47.2 U1.25(JTAG_TCKC)
CC1350_TMS: CR8.7(IO6) P4.10 P5.2 R46.2 U1.24(JTAG_TMSC)
CC1350_TXD: J1.5 P4.14 U1.8(DIO_3)
CC1350_VDD: C30.1 CR8.8(VCC) FL1.2 J1.1 P1.1 P4.18 P5.1 P10.3 R2.2 R3.2 R11.2 R59.2 R60.2 U4.8(VCC)
DCDC_SW: L1.1 U1.33(DCDC_SW)
DIO1_RF_SW: J1.20 U1.6(DIO_1) U11.6(CTL)
DIO4_SCL: J1.17 R2.1 U1.9(DIO_4)
DIO5_SDA: J1.19 R3.1 U1.10(DIO_5)
DIO6_RLED: J2.3 P6.2 U1.11(DIO_6)
DIO7_GLED: J2.1 P6.4 U1.12(DIO_7)
DIO8_MISO: J2.14 U1.14(DIO_8) U4.2(SO/SIO1)
DIO9_MOSI: J2.12 U1.15(DIO_9) U4.5(SI/SIO0)
DIO10_SCLK: J1.13 U1.16(DIO_10) U4.6(SCLK)
DIO11_CS: J2.6 U1.17(DIO_11)
DIO12: J2.4 U1.18(DIO_12)
DIO13_BTN1: J2.16 R56.2 U1.19(DIO_13)
DIO14_BTN2: J2.18 R55.2 U1.20(DIO_14)
DIO15: J2.20 U1.21(DIO_15)
DIO16_TDO: CR8.5(IO4) P4.6 P5.6 R48.2 U1.26(DIO_16)
DIO17_TDI: CR8.3(IO3) P4.4 P5.8 R49.2 U1.27(DIO_17)
DIO19_CTS: J2.7 U1.29(DIO_19)
DIO20_FLASH_CS: J2.5 R11.1 U1.30(DIO_20) U4.1(NCS)
DIO21: J1.15 U1.31(DIO_21)
DIO22: J1.9 U1.32(DIO_22)
DIO23_ANALOG: J1.3 U1.36(DIO_23)
DIO24_ANALOG: J1.11 U1.37(DIO_24)
DIO25_ANALOG: J1.6 U1.38(DIO_25)
DIO26_ANALOG: J1.8 U1.39(DIO_26)
DIO27_ANALOG: J1.10 U1.40(DIO_27)
DIO28_ANALOG: J1.12 U1.41(DIO_28)
DIO29_ANALOG: J1.14 U1.42(DIO_29)
IRSTN: P8.10(5) R20.2
ITCK: P8.4(2) U5.100(PC0/TCK/SWCLK)
ITDI: P8.8(4) U5.98(PC2/TDI)
ITDO: P8.6(3) U5.97(PC3/TDO/SWO)
ITMS: P8.2(1) U5.99(PC1/TMS/SWDIO)
LP_RESET: J2.10 R51.1
USB_DM: CR6.5 J6.2(D-) U5.93(PL7/USB0DM)
USB_DP: CR6.4 J6.3(D+) U5.94(PL6/USB0DP)
USB_ID: CR6.2 J6.4(ID) R19.2
USB_VBUS: C48.1 CR6.6 J6.1(VCC) P4.19 R22.2 R66.1 U7.1(IN#1) U7.2(IN#2) U7.8(EN)
V-SENSE: C53.1 C55.1 C57.1 CR7.8(VCC) P7.1 P10.2 U8.2(VCCB) U9.2(VCCB) U10.2(VCCB)
XDS_RESET: R58.1 U5.40(PA6) U10.1(1NOE) U10.6(1A1)
XDS_RESET_LS: CR7.2(IO2) P4.11 P7.10 R57.2 U10.15(1B1)
XDS_RX: U5.33(PA0/U0RX) U8.8(2A1)
XDS_RX_LS: P4.13 R61.2 U8.13(2B1)
XDS_SWO: U5.25(PC4/C1-) U8.9(2A2)
XDS_SWO_LS: P4.1 R62.2 U8.12(2B2)
XDS_TCK: U5.35(PA2/SSI0CLK) U9.6(1A1)
XDS_TDI: U5.38(PA5/SSI0XDAT1) U9.7(1A2)
XDS_TDI_LS: CR7.3(IO3) P4.3 P7.8 U9.14(1B2)
XDS_TDO: U5.37(PA4/SSI0XDAT0) U9.9(2A2)
XDS_TDO_LS: CR7.5(IO4) P4.5 P7.6 R63.2 U9.12(2B2)
XDS_TMS: U5.36(PA3/SSI0FSS) U10.8(2A1)
XDS_TMS_DIR: U5.24(PC5/C1+) U10.5(2DIR)
XDS_TMS_LS: CR7.7(IO6) P4.9 P7.2 R65.2 U10.13(2B1)
XDS_TX: U5.34(PA1/U0TX) U8.6(1A1)
XDS_TX_LS: P4.15 U8.15(1B1)
XDS_VCC: C35.1 C36.1 C37.1 C38.1 C39.1 C40.1 C41.1 C42.1 C47.1 C49.1 C52.1 C54.1 C56.1 P4.17 P8.1(6) P10.1 R17.2 R18.2 R27.1 R30.2 R31.2 R33.2 R39.1 R58.2 U5.7(VDD#7) U5.8(VDDA) U5.16(VDD#16) U5.26(VDD#26) U5.28(VDD#28) U5.39(VDD#39) U5.47(VDD#47) U5.51(VDD#51) U5.52(VDD#52) U5.69(VDD#69) U5.79(VDD#79) U5.90(VDD#90) U5.101(VDD#101) U5.113(VDD#113) U5.122(VDD#122) U7.3(OUT#3) U7.4(OUT#4) U8.3(VCCA) U8.4(1DIR) U9.3(VCCA) U9.4(1DIR) U10.3(VCCA) U10.4(1DIR)
N1013277: U1.46(X24M_N) Y2.3
N1013855: C11.1 L12.1 L30.2 U11.10(PORT3-)
N1013859: C22.1 L27.1 L30.1 U11.1(PORT3+)
N1013907: C12.1 C22.2 L12.2 L13.1
N1013927: C13.1 L13.2 L14.1
N1013977: A1.1(FEED/GND_1) C71.2 L33.1
N1014101: C17.1 U1.4(X32K_Q1) Y1.1
N1014113: C18.1 U1.5(X32K_Q2) Y1.2
N1018952: U1.47(X24M_P) Y2.1
N1105722: CR1.2(A) R15.1
N1105771: CR2.2(A) R14.1
N1105824: P6.1 R14.2
N1106228: P6.3 R15.2
N1176544: J2.13 R46.1
N1176548: J2.15 R47.1
N1176568: J2.17 R48.1
N1177007: J2.19 R49.1
N1240270: CR7.6(IO5) P4.7 P7.4 U9.15(1B1)
N1288065: R55.1 SW2.3
N1288098: R56.1 SW1.4
N1299607: J2.11 R52.2
N1384129: R57.1 SW3.3
N1393569: C19.1 U1.23(DCOUPL)
N1403554: C58.1 C65.1 L28.2 L29.2 U1.3(RX_TX)
N1414078: C14.1 C15.1 C69.1 L14.2
N1417883: C63.1 L28.1 U1.1(RF_P)
N1418253: C64.1 L29.1 U1.2(RF_N)
N1419138: C21.2 L21.1 L31.2 U11.4(PORT2-)
N1419146: C60.1 L11.1 L31.1 U11.5(PORT2+)
N1419182: C60.2 C61.1 L21.2 L25.1
N1419210: C62.2 L25.2 L26.1
N1419230: A2.1(FEED_1) C24.1 C59.1
N1419286: C24.2 C67.1 C68.2 L26.2
N1420906: C64.2 U11.7(PORT1+)
N1421284: R67.2 R68.2 R69.1 U11.9(VDD)
N1433060: C15.2 C71.1 L32.1
N1447877: R59.1 U4.3(NWP/SIO2)
N1447884: R60.1 U4.7(NRST/SIO3)
N1465309: C63.2 U11.8(PORT1-)
N1466589: C69.2 P11.1
N1466981: C67.2 P12.1
N1587996: R17.1 R20.1 R21.1 U5.70(NRST)
N1588002: R30.1 U5.60(PK7)
N1588004: C47.2 R33.1 R34.2 U7.5(FB)
N1588016: R28.2 U5.59(RBIAS)
N1588028: R22.1 R24.1 U5.1(PD0/AIN15)
N1588034: C34.1 U5.89(OSC1) Y3.3
N1588038: C33.1 U5.88(OSC0) Y3.1
N1588066: C32.1 C50.1 R18.1 U5.9(VREFA+) U6.3(CATHODE)
N1588110: R19.1 U5.95(PB0/USB0ID)
N1588130: R39.2 U5.63(PK4)
N1588132: R29.1 U5.61(PK6)
N1588134: R27.2 U5.62(PK5)
N1588248: C46.1 R31.1 U5.68(VBAT)
N1588328: R23.2 U5.3(PD2/AIN13)
N1588330: R25.2 U5.4(PD3/AIN12)
N1588336: CR6.1 J6.M1(SHIELD1) J6.M2(SHIELD2) R32.2
N1588554: C70.1 R66.2 U5.96(PB1/USB0VBUS)
N15894280: CR4.2(A) R23.1
N15894940: CR5.2(A) R25.1

Pads without a net: CR7 1; CR8 1; FIDU1 1; FIDU2 1; FIDU3 1; FIDU4 1; FIDU5 1; FIDU6 1; J1 18; J2 8; LBL4 1; P5 7; P7 7; P8 7; U5 2 5 6 11 12 13 14 15 18 19 20 21 22 23 27 29 30 31 32 41 42 43 44 45 46 49 50 53 54 56 57 65 67 71 72 73 74 75 76 77 78 81 82 83 84 85 86 91 92 102 103 104 105 106 107 108 109 110 111 112 116 117 118 119 120 121 123 124 125 126 127 128; U6 2 4 5; U7 7; U8 14; U9 8; U10 14

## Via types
v1: diameter 0.406, hole 0.203, TOP to BOTTOM, 1023 vias
v2: diameter 0.787, hole 0.406, TOP to BOTTOM, 21 vias
v3: diameter 0.508, hole 0.254, TOP to BOTTOM, 8 vias
v4: diameter 0.508, hole 0.203, TOP to BOTTOM, 28 vias

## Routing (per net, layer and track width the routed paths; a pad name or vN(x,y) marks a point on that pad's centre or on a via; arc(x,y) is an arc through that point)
+5V: length 54.3
  L3 w0.508: 9.09,70.41 9.04,70.46 5.36,70.46 3.43,68.53 3.43,36.37 4.39,35.41 5.16,35.41 5.18,35.43 P2.1 ; 9.09,70.41 8.92,70.23 J1.2 ; 9.09,70.41 14,75.31 P4.20
GND: length 551.1
  TOP w0.152: 20.29,82.8 R61.1 20.8,83.31 ; 30,28.06 U11.3 29.82,28.06 ; 7.42,109.17 Y3.2 8.38,108.31 ; 45.67,72.22 P5.9 ; P5.9 45.13,73.51 ; P5.9 45.67,74.79 ; 4.65,116.71 MH3.1 2.49,114.55 ; 8.66,107.47 Y3.4 8.66,106.6 ; 19.82,21.33 20.18,20.97 20.54,21.33 ; C39.2 20.24,95.68 19.96,95.4 U5.48 18.06,95.4 17.93,95.28 ; C39.2 21.21,95.17 ; C39.2 20.7,95.17 ; 2.21,91.34 CR5.1 2.21,90.07 ; 19.3,85.78 19.1,85.98 U8.7 ; 12.62,106.4 C49.2 ; C49.2 12.62,107.42 ; C49.2 13.13,106.91 ; 2.77,78.21 SW1.1 2.01,79.17 ; U10.16 24.26,84.37 ; U10.16 24.26,83.49 ; U10.16 24.41,84.07 ; 27.28,84.71 U9.1 ; U9.1 27.99,84.68 27.91,84.61 27.91,84.07 ; U9.1 27.28,84.89 ; 20.6,86.82 C52.2 ; C52.2 21.11,87.33 ; C52.2 21.62,86.82 ; R65.1 47.4,81.1 ; R65.1 46.38,81.1 ; R65.1 46.89,80.59 ; 25.09,19.51 L33.2 ; L33.2 26.11,19.51 ; L33.2 25.6,20.02 ; R32.1 16.21,112.12 ; R32.1 15.7,111.61 ; R32.1 15.19,112.12 ; 14.27,106.4 R21.2 13.76,105.89 ; 13.62,111.3 C48.2 13.11,110.79 ; 40.11,75.56 CR8.4 40.11,75.97 ; 21.92,84.35 U10.12 21.92,84.71 ; 36.73,28.9 C17.2 37.24,29.92 ; U6.1 v1(12.8,86.31) ; U6.1 11.64,86.31 11.43,86.11 11.33,86.11 11.32,86.11 11.22,86.11 ; U6.1 12.79,86.77 ; U6.1 12.09,86.77 11.71,87.15 U5.17 11.71,87.96 ; 19.2,102.16 U5.64 18.2,101.8 ; 11.81,101.98 11.71,102.08 U5.80 11.71,104.17 11.4,104.47 ; 21.69,95.17 C40.2 22.2,95.68 ; 43.69,86.51 P7.5 42.62,86.51 ; SW1.3 4.73,76.94 ; SW1.3 3.81,77.65 ; SW1.3 2.89,76.94 ; SW1.3 3.81,76.22 ; 22.96,33.22 Y2.4 ; Y2.4 22.96,35 ; Y2.4 23.75,34.11 ; Y2.4 22.17,34.11 ; 33.61,23.25 33.97,23.61 ; 33.97,23.61 33.61,23.97 ; 33.97,23.61 34.33,23.25 ; 5.21,104.73 C70.2 4.7,104.73 ; 25.48,36.35 Y2.2 23.9,36.35 ; C68.1 38.28,18.75 ; C68.1 38.66,18.41 ; C68.1 37.94,19.13 ; 37.24,29.94 C18.2 ; C18.2 37.75,30.45 ; C18.2 36.73,30.45 ; 16.92,86.41 C35.2 16.41,85.9 ; 5.53,37.11 P2.2 7.27,38.84 ; 48.92,34.65 v1(48.92,34.24) 48.92,33.83 ; 30.2,45.04 C7.2 29.95,45.04 ; 27.89,45.11 C6.2 28.6,45.75 ; L32.2 22.91,19.51 ; L32.2 22.4,20.02 ; L32.2 21.89,19.51 ; 24.58,84.2 C55.2 25.1,83.69 ; 36.64,15.63 A2.3 38.14,15.63 ; 12.32,79.48 11.51,78.66 ; 3.88,85.6 R24.2 4.39,85.09 ; 22.53,101.12 R29.2 22.53,100.61 ; 52.96,38.84 P1.2 51.23,37.11 ; 53.64,116.71 MH4.1 55.8,114.55 ; 13.13,30.79 v1(9.7,29.57) 9.7,30.79 ; 40.08,86.51 P7.9 41.15,86.51 ; 11.22,86.11 11.22,86 C50.2 10.8,85.57 10.8,86.49 C32.2 11.22,86.11 ; 17.3,103.33 U5.66 v1(17.3,102.01) ; 20.25,86.54 U8.5 19.89,87.12 ; 19.28,84.71 U8.1 ; U8.1 19.91,84.61 19.91,84.07 ; U8.1 19.28,84.89 ; 28.6,86.82 C56.2 ; C56.2 29.62,86.82 ; C56.2 29.11,87.33 ; 49.66,32.56 U4.4 50.07,33.05 ; 31.85,30.45 C58.2 31.34,29.94 ; 6.47,86.51 C41.2 6.47,86 ; 26.04,28.16 26.4,27.8 ; 26.4,27.8 26.04,27.44 ; 26.4,27.8 26.76,28.16 ; 36.98,22.74 C62.1 37.7,22.02 ; 15.11,32.43 CR1.1 ; CR1.1 15.11,33.71 ; CR1.1 15.75,33.07 ; 10.59,77.75 11.46,78.61 10.59,79.48 ; 34.8,82.75 R62.1 ; R62.1 34.29,83.26 ; R62.1 34.82,83.26 v1(36.53,84.96) ; 14.2,110.64 U7.9 12.21,107.64 ; 29.11,83.69 C57.2 ; C57.2 29.62,84.2 ; C57.2 28.6,84.2 ; 52.1,41.6 P1.3 53.18,40.51 ; 0.89,92.61 C45.2 1.4,92.1 ; v1(8.94,105.64) 9.65,106.35 9.65,106.55 9.47,106.55 v1(8.53,107.49) 7.75,108.28 7.32,108.28 7.26,108.33 ; v1(8.94,105.64) 8.56,105.26 C34.2 ; v1(8.94,105.64) 9.3,105.28 C33.2 ; 2.8,95 U5.114 4.82,95 ; 24.58,86.82 C54.2 ; C54.2 25.61,86.82 ; C54.2 25.1,87.33 ; 2.77,71.45 SW1.2 2.01,70.48 ; 30.15,28.06 U11.2 29.79,28.06 ; 42.19,16.25 C59.2 42.19,17.27 ; C46.2 18.29,106.33 ; C46.2 17.78,105.82 ; C46.2 18.8,105.82 ; 9.7,19.25 P11.M2 13.13,20.47 ; 7.9,105.77 C34.2 ; C34.2 8.41,105.77 ; 27.91,84.07 28.22,84.07 v1(28.5,83.79) ; 27.91,84.07 U9.16 ; SW3.4 19.03,115.6 ; SW3.4 18.31,116.51 ; SW3.4 17.6,115.6 ; 28.13,25.38 28.49,25.74 ; 28.49,25.74 28.85,25.38 ; 28.49,25.74 28.85,26.1 ; 41.78,80.31 R63.1 42.29,80.83 ; 6.99,85.09 C42.2 6.47,85.6 ; 27.89,87.12 U9.5 28.25,86.54 ; 24.47,25.29 24.83,25.65 ; 24.47,25.29 24.11,24.93 ; 24.47,25.29 24.11,25.65 ; R34.1 15.69,108.92 15.43,108.92 15.32,108.81 U7.6 ; R34.1 15.95,109.43 ; R34.1 15.7,109.43 ; C8.2 29.64,48.21 ; C8.2 29,47.5 ; C8.2 30.28,47.5 ; 46.61,34.52 C30.2 ; C30.2 47.63,34.52 ; C30.2 47.12,34.01 ; 17.63,105.41 C38.2 17.63,104.9 ; 17.04,117.4 18.01,117.4 ; 17.04,117.4 17.04,116.63 ; 17.04,117.4 17.04,118.16 ; 5.53,39.65 P2.3 7.27,41.38 ; U5.10 8.92,89.13 v1(8.99,89.2) v1(11.81,89.2) 11.68,89.08 11.68,88.14 ; 38.43,40.92 C4.2 38.43,40.16 ; C33.2 8.96,105.79 ; C33.2 9.5,105.28 ; C33.2 8.96,105.54 ; P5.5 43.13,74.79 ; P5.5 42.59,73.51 ; P5.5 43.13,72.22 ; P5.5 43.67,73.51 ; 36.4,41.91 C19.2 36.4,42.42 ; U9.16 28.25,84.37 ; U9.16 28.25,83.78 ; 54.69,76.27 SW2.4 ; SW2.4 55.6,76.99 ; SW2.4 54.69,77.7 ; SW2.4 53.77,76.99 ; 39.97,15.69 A2.2 38.85,15.63 ; 24.89,30.3 R68.1 25.4,29.79 ; 2.41,98.57 C37.2 1.9,99.09 ; 26.7,83.49 U9.13 26.34,84.07 ; 25.88,36.65 C16.2 26.39,36.65 ; 22.83,117.4 SW3.1 ; SW3.1 24.77,117.4 ; SW3.1 23.8,118.16 ; SW3.1 23.8,116.63 ; U8.16 20.25,84.37 ; U8.16 19.91,84.07 ; U8.16 20.25,83.49 ; 55.73,70.53 SW2.1 55.73,71.5 ; 11.46,82.24 11.46,81.15 10.59,80.29 ; 1.8,96.42 C36.2 2.31,96.93 ; 19.91,84.07 20.4,84.07 ; U5.58 18.01,99.42 ; 1.4,94.92 C43.2 0.89,94.41 ; 45.36,30.53 P12.M2 48.79,30.53 ; 27.71,30.43 C65.2 ; C65.2 28.22,29.92 ; C65.2 28.73,30.43 ; 37.82,35.1 C3.2 38.33,35.1 ; 25.78,38.18 C5.2 25.78,37.41 ; 22.41,98.81 R28.1 21.89,98.3 ; 0.99,90.07 CR4.1 0.99,91.34 ; 41.86,72.22 P5.3 ; P5.3 41.32,73.51 ; P5.3 42.4,73.51 ; P5.3 41.86,74.79 ; 26.26,44.15 C20.2 26.77,43.64 ; 44.96,86.51 P7.3 43.89,86.51 ; 20.21,98.22 U5.55 18.2,98.22 ; 30.57,25.6 C21.1 30.93,25.24 ; 34.08,27.65 L11.2 33,28.01 ; 45.36,19 v1(48.79,20.22) 45.36,20.22 ; 26.95,34.14 C9.2 26.18,34.14 ; 3.88,82.49 MH5.1 2.11,80.73 ; 9.78,66.78 J1.4 8.05,65.05 ; 56.49,79.23 SW2.2 55.73,78.26 ; 0.89,93.5 C44.2 0.89,94.01 ; 20.6,84.2 C53.2 ; C53.2 21.62,84.2 ; C53.2 21.11,83.69 ; CR2.1 13.16,33.1 ; CR2.1 12.52,33.73 ; CR2.1 12.52,32.46 ; 22.67,23.49 21.95,22.77 ; 23.09,85.9 23.11,85.93 U10.7 ; 51.25,67.59 J2.2 52.99,69.32 ; 39.6,15.7 39.6,15.75
  TOP w0.203: U11.2 U11.3 30.18,27.97 v1(30.02,27.81) 30.02,27.89 29.85,28.07 29.85,28.42 U11.2
  TOP w0.254: U4.4 49.66,33.5 v1(48.92,34.24) ; C4.2 v1(38.51,40.41) ; C19.2 v1(37.54,42.42) ; C3.2 v1(38.4,35.61)
  TOP w0.305: 51.89,118.31 52.1,118.11 53.7,118.11 ; 38.85,15.24 A2.2 39.6,15.7 39.78,15.88 ; 38.3,18.75 38.28,18.75 37.77,18.24 ; 38.3,18.75 C68.1 38.28,18.77 37.82,19.23 ; 38.3,18.75 38.76,18.29 ; Y2.2 24.69,37.52 v1(24.71,37.54) ; 37.34,22.35 37.34,22.3 37.8,21.84 ; 37.34,22.35 C62.1 37.85,22.89 ; 37.34,22.35 v1(36.83,22.86) ; v1(24.08,25.73) 24.33,25.48 24.49,25.27 ; v1(21.79,22.81) 21.84,22.81 22.15,23.11 22.33,23.11 ; 24.49,25.27 24.47,25.29 ; 24.49,25.27 24.47,25.29 ; 24.49,25.27 24.54,25.32 24.54,25.55 v1(24.79,25.81) ; 24.49,25.27 24.47,25.29 ; 24.49,25.27 24.31,25.27 24,24.97 v1(23.93,24.97) ; v1(25.65,37.95) 25.68,37.92 C5.2 26.29,37.26 C16.2 25.78,37.16 v1(25.73,37.21) ; C59.2 v1(42.42,16.76) 42.44,16.76 ; C59.2 41.68,17.48 ; C59.2 41.68,16.1 ; J2.2 56.16,68.45 56.49,68.78 SW2.1 ; v1(25.58,43.64) C20.2 ; 33.88,28.17 L11.2 ; L11.2 33.34,27.65 v1(32.87,28.12) ; L11.2 33.86,27.15 ; v1(28.68,45.92) 28.68,45.19 C6.2 ; v1(37.95,30.43) 37.11,30.43 v1(36.58,29.9) 37.06,29.41 C17.2 v1(37.97,29.41) ; 33.95,23.51 33.95,23.61 ; 33.95,23.51 v1(33.5,23.06) ; 33.95,23.51 34.05,23.51 v1(34.44,23.11) ; 33.95,23.61 33.97,23.61 ; 33.95,23.61 33.5,24.05 ; v1(22.63,23.65) 22.63,23.6 22.33,23.29 22.33,23.11 ; 57.4,118.31 MH4.1 ; CR2.1 v1(11.79,33.1) ; 53.8,112.9 54.51,113.61 54.51,114.71 ; 22.94,34.09 22.78,33.93 v1(21.84,33.93) ; 22.94,34.09 v1(22.94,32.89) ; 22.94,34.09 Y2.4 ; 20.19,21.06 20.19,20.96 20.18,20.97 ; 20.19,21.06 20.19,21.13 20.47,21.41 v1(20.47,21.51) ; 20.19,21.06 v1(19.81,21.44) ; v1(28.88,26.21) 28.8,26.14 28.8,26.11 28.47,25.76 ; 22.33,23.11 22.31,23.13 ; 22.33,23.11 22.31,23.13 ; 22.31,23.13 v1(21.89,23.55) ; 28.47,25.76 28.85,25.35 v1(28.88,25.32) ; 28.47,25.76 28.49,25.74 ; 28.47,25.76 28.09,25.35 v1(28.07,25.32) ; C30.2 47.4,34.24 v1(48.92,34.24) ; C21.1 v1(30.81,25.1) ; C21.1 v1(31.78,25.12) ; C21.1 v1(30.81,26.09) ; 38.23,15.24 A2.3 ; A2.3 37.39,15.75 ; A2.3 36.64,15.24 ; 26.4,27.8 26.42,27.79 ; 26.42,27.79 26.11,28.14 26.11,28.17 v1(26.04,28.24) ; 26.42,27.79 v1(25.98,27.36) ; 57.3,114.6 57.3,113.11 ; v1(25.98,34.24) 26.39,34.65 C9.2 26.7,33.96 v1(26.67,33.93) ; CR1.1 v1(14.3,33.07) ; J6.5 12.7,113 v1(13.51,112.19) 13.11,111.79 13.11,111.33 ; v1(11.46,111.15) 11.3,111.3 CR6.3 ; v1(26.82,28.24) 26.42,27.84 ; v1(29.39,45.21) v1(29.9,45.21) v1(29.9,45.69) v1(29.39,45.69) v1(29.39,45.21)
  TOP w0.406: C6.2 29.29,45.11 v1(29.39,45.21) 29.69,44.91 C7.2
  TOP w0.508: v1(9.04,30.86) 9.04,30.23 v1(9.7,29.57) ; 11.46,79.82 11.46,81.15 ; 11.46,81.15 10.44,81.15 ; 11.46,81.15 11.48,81.15 ; P1.2 53.18,37.97 ; P1.2 52.1,39.31 ; P1.2 52.1,36.89 ; P1.2 51.01,37.97 ; v1(49.71,18.92) 49.71,19.3 v1(48.79,20.22) ; v1(12.55,19.81) 12.5,19.76 v1(12.5,19.18) ; v1(48.87,29.51) 48.21,30.18 v1(48.21,30.61) ; 10.08,20.37 9.8,20.37 P11.M2 ; 10.08,20.37 v1(13.21,20.37) ; 10.08,20.37 10.67,19.79 v1(10.67,19.18) ; P2.2 5.32,37.97 ; P2.2 6.4,36.89 ; P2.2 7.48,37.97 ; P2.2 P2.3 ; v1(9.7,29.57) 11.25,29.57 ; v1(9.7,29.57) 10.49,30.35 v1(10.49,30.86) ; v1(9.7,29.57) 8.74,29.57 7.44,30.86 v1(7.34,30.86) ; v1(45.26,19.94) 45.57,19.94 45.67,19.84 46.18,19.84 46.38,20.02 46.46,19.94 47.47,19.94 46.94,19.41 v1(46.94,18.9) ; v1(8.99,19.18) 8.99,19.76 P11.M2 ; 11.25,29.57 11.94,30.25 v1(11.94,30.86) ; 11.25,29.57 v1(13.21,29.57) ; J2.2 51.04,68.45 ; J2.2 52.12,67.37 ; J2.2 52.12,69.54 ; 55.98,114.25 MH4.1 53.16,116.79 ; MH5.1 3,82.72 ; MH5.1 1.89,81.61 ; MH5.1 4.1,81.61 ; MH5.1 3,80.5 ; P11.M2 8.59,20.47 7.34,19.23 v1(7.34,19.18) ; v1(45.59,30.43) 46.08,29.95 v1(46.28,29.95) ; P2.3 7.48,40.51 ; P2.3 6.4,41.6 ; P2.3 5.32,40.51 ; P12.M2 49.68,30.2 v1(49.68,30.61) ; P12.M2 48.11,29.31 v1(46.81,30.61) ; P12.M2 48.77,29.34 ; 11.46,78.61 12.54,78.61 ; 11.46,78.61 11.51,78.66 ; 11.46,78.61 11.46,77.53 ; 11.46,78.61 11.46,79.7 ; 11.46,78.61 10.44,78.61 ; 12.52,81.15 11.48,81.15 ; 11.48,81.15 11.48,82.14 ; C8.2 29.64,45.95 v1(29.9,45.69) ; P1.3 v1(53.87,40.44) ; P1.3 52.1,39.43 ; P1.3 51.01,40.51 ; P1.3 51.99,41.83 ; 48.77,29.34 46.76,29.34 46.74,29.36 45.92,29.36 45.9,29.34 v1(45.29,29.34) ; 48.77,29.34 48.67,29.44 ; v1(48.79,20.22) 48.79,19.48 48.49,19.18 v1(48.49,18.92) ; v1(48.79,20.22) 49.73,20.22 50.67,19.28 50.67,19.23 50.83,19.08 v1(50.83,18.92) ; v1(51.21,29.95) 51.18,29.97 v1(51.18,30.61) ; v1(10.77,65.91) J1.4 ; J1.4 7.83,65.91 ; J1.4 8.92,67
  L2 w0.152: J2.2 52.12,69.54 ; J2.2 52.12,67.37 ; J2.2 51.04,68.45 ; J2.2 53.2,68.45 ; P1.2 52.1,39.06 ; P1.2 51.01,37.97 ; P1.2 53.18,37.97 ; P1.2 52.1,36.89 ; MH5.1 3,82.72 ; MH5.1 4.1,81.61 ; MH5.1 3,80.5 ; MH5.1 1.89,81.61 ; 2.49,114.55 MH3.1 4.65,116.71 ; 6.4,36.89 P2.2 ; P2.2 5.32,37.97 ; P2.2 6.4,39.06 ; P2.2 7.48,37.97 ; 6.4,39.43 P2.3 ; P2.3 7.48,40.51 ; P2.3 5.32,40.51 ; P2.3 6.4,41.6 ; 52.1,39.43 P1.3 ; P1.3 51.01,40.51 ; P1.3 52.1,41.6 ; P1.3 53.18,40.51 ; 11.46,81.15 12.54,81.15 ; 11.46,81.15 11.46,80.07 ; 11.46,81.15 11.46,82.24 ; 11.46,81.15 10.37,81.15 ; 11.46,77.53 11.46,78.61 ; 11.46,78.61 12.54,78.61 ; 11.46,78.61 10.37,78.61 ; 11.46,78.61 11.46,79.7 ; J1.4 10,65.91 ; J1.4 8.92,64.83 ; J1.4 7.83,65.91 ; J1.4 8.92,67 ; 55.8,114.55 MH4.1 53.64,116.71
  L2 w0.381: 35.51,39.12 34.39,40.21
  L3 w0.152: 10.37,81.15 11.46,81.15 ; 11.46,81.15 11.46,80.07 ; 11.46,81.15 12.54,81.15 ; 11.46,81.15 11.46,82.24 ; 52.12,67.37 J2.2 ; J2.2 51.04,68.45 ; J2.2 52.12,69.54 ; J2.2 53.2,68.45 ; 52.1,39.43 P1.3 ; P1.3 52.1,41.6 ; P1.3 53.18,40.51 ; P1.3 51.01,40.51 ; P2.3 6.4,41.6 ; P2.3 5.32,40.51 ; P2.3 6.4,39.43 ; P2.3 7.48,40.51 ; MH5.1 4.1,81.61 ; MH5.1 1.89,81.61 ; MH5.1 3,80.5 ; MH5.1 3,82.72 ; 11.46,78.61 12.54,78.61 ; 11.46,78.61 11.46,79.7 ; 11.46,78.61 11.46,77.53 ; 11.46,78.61 10.37,78.61 ; P2.2 7.48,37.97 ; P2.2 5.32,37.97 ; P2.2 6.4,36.89 ; P2.2 6.4,39.06 ; 52.1,36.89 P1.2 ; P1.2 53.18,37.97 ; P1.2 52.1,39.06 ; P1.2 51.01,37.97 ; 8.92,64.83 J1.4 ; J1.4 8.92,67 ; J1.4 10,65.91 ; J1.4 7.83,65.91 ; 4.65,116.71 MH3.1 2.49,114.55 ; 53.64,116.71 MH4.1 55.8,114.55
  L3 w0.305: v1(28.22,29.82) C65.2 28.19,30.4 v1(27.51,30.4) ; v1(31.62,29.84) 31.34,30.12 31.34,30.43 32,30.43 v1(32.03,30.4)
  BOTTOM w0.152: 4.03,107.47 v1(3.38,107.47) 2.82,106.91 ; P1.2 53.18,37.97 ; P1.2 52.1,36.89 ; P1.2 52.1,39.06 ; P1.2 51.01,37.97 ; 1.89,81.61 MH5.1 ; MH5.1 3,82.72 ; MH5.1 3,80.5 ; MH5.1 4.1,81.61 ; 51.01,40.51 P1.3 ; P1.3 52.1,39.43 ; P1.3 52.1,41.6 ; P1.3 53.18,40.51 ; J1.4 10,65.91 ; J1.4 8.92,67 ; J1.4 7.83,65.91 ; J1.4 8.92,64.83 ; 1.46,108.74 v1(2.11,108.74) 1.55,108.18 ; 11.46,81.15 12.54,81.15 ; 11.46,81.15 11.46,82.24 ; 11.46,81.15 10.37,81.15 ; 11.46,81.15 11.46,80.07 ; 5.32,40.51 P2.3 ; P2.3 6.4,39.43 ; P2.3 6.4,41.6 ; P2.3 7.48,40.51 ; 1.46,111.28 v1(2.11,111.28) 1.55,110.72 ; 51.04,68.45 J2.2 ; J2.2 53.2,68.45 ; J2.2 52.12,67.37 ; J2.2 52.12,69.54 ; 2.49,114.55 MH3.1 4.65,116.71 ; 5.32,37.97 P2.2 ; P2.2 6.4,39.06 ; P2.2 7.48,37.97 ; P2.2 6.4,36.89 ; 10.37,78.61 11.46,78.61 ; 11.46,78.61 12.54,78.61 ; 11.46,78.61 11.46,79.7 ; 11.46,78.61 11.46,77.53 ; 53.64,116.71 MH4.1 55.8,114.55
  vias: v1(0.79,65.28) v1(0.76,62.05) v1(0.76,59.77) v1(0.76,56.64) v1(0.81,53.26) v1(0.76,50.72) v1(0.76,47.93) v1(0.76,44.73) v1(0.76,15.85) v1(1.4,95) v1(1.4,69.9) v1(1.5,38.91) v1(1.6,96.49) v1(1.6,91.59) v1(1.93,51.97) v1(1.91,49.17) v1(1.91,46.15) v1(2.03,60.81) v1(2.01,57.94) v1(1.96,54.81) v1(2.11,67.44) v1(2.06,63.6) v1(2.31,98.4) v1(2.49,40.79) v1(2.59,77.22) v1(3.53,70.18) v1(3.61,85.7) v1(3.78,15.85) v1(4.19,105.61) v1(4.27,66.85) v1(4.27,64.36) v1(4.34,61.85) v1(4.34,56.64) v1(4.34,54.05) v1(4.27,51.36) v1(4.34,49.23) v1(4.34,46.69) v1(4.42,59.23) v1(4.42,43.97) v1(4.5,84.61) v1(4.62,36.65) v1(4.62,34.29) v1(4.7,105) v1(4.67,39.07) v1(4.88,42.27) v1(5.03,76.99) v1(5.11,95.3) v1(5.18,74.04) v1(5.33,78.61) v1(6.4,86) v1(6.5,15.85) v1(6.76,72.16) v1(6.86,78.61) v1(6.91,75.23) v1(7.11,84.61) v1(7.06,42.88) v1(7.26,30.15) v1(7.34,29.34) v1(7.29,20.68) v1(7.34,19.81) v1(7.34,17.37) v1(7.37,33.12) v1(7.62,77.04) v1(8.1,16.64) v1(8.2,109.25) v1(8.23,31.93) v1(8.15,18.26) v1(8.28,72.16) v1(8.26,34.14) v1(8.38,39.37) v1(8.61,36.4) v1(8.92,33.2) v1(9.07,41.38) v1(9.27,109.37) v1(9.47,75.18) v1(9.55,37.95) v1(9.68,20.5) v1(9.83,76.56) v1(9.8,72.16) v1(9.78,42.93) v1(9.78,31.95) v1(9.91,78.21) v1(9.88,34.24) v1(9.91,18.34) v1(9.93,17.12) v1(9.86,15.85) v1(10.21,61.34) v1(10.31,70.38) v1(10.29,62.69) v1(10.31,60.12) v1(10.31,57.61) v1(10.39,64.16) v1(10.41,53.85) v1(10.41,52.55) v1(10.44,51.31) v1(10.54,56.39) v1(10.46,50.01) v1(10.46,48.18) v1(10.52,39.47) v1(10.62,33.25) v1(10.74,35.84) v1(10.97,104.57) v1(11.3,86.11) v1(11.28,32.03) v1(11.3,16.66) v1(11.46,34.29) v1(11.66,44.91) v1(11.81,102.01) v1(11.84,72.16) v1(11.94,58.98) v1(11.86,18.47) v1(12.5,30.2) v1(12.55,29.41) v1(12.6,70.38) v1(12.62,50.04) v1(12.57,20.62) v1(12.73,53.9) v1(12.8,32.03) v1(12.85,76.73) v1(12.85,75.46) v1(12.9,62.87) v1(12.88,52.6) v1(12.88,17.48) v1(13.03,15.85) v1(13.34,54.97) v1(13.36,72.16) v1(13.39,31.06) v1(13.69,27.97) v1(13.69,26.29) v1(13.69,22.2) v1(13.79,111.3) v1(13.79,45.44) v1(13.94,47.96) v1(13.89,23.77) v1(14.05,32.05) v1(14.15,17.86) v1(14.22,57.61) v1(14.22,30.12) v1(14.22,19.76) v1(14.3,106.6) v1(14.3,16.61) v1(14.38,64.24) v1(14.43,60.1) v1(14.5,112.29) v1(14.45,61.37) v1(14.73,27.23) v1(14.76,22.76) v1(14.76,20.83) v1(14.88,70.38) v1(15.14,76.73) v1(15.14,74.96) v1(15.14,73.43) v1(15.09,31.12) v1(15.49,28.8) v1(15.65,72.16) v1(15.57,26.29) v1(15.6,23.8) v1(15.65,21.89) v1(15.57,15.85) v1(15.7,64.21) v1(15.75,61.44) v1(15.72,19.76) v1(15.8,111.4) v1(15.98,69.32) v1(16,67.94) v1(15.95,65.66) v1(16,58.88) v1(16.03,17.91) v1(16.08,48.01) v1(16.05,45.47) v1(16.13,32.03) v1(16.23,36.98) v1(16.15,35.48) v1(16.31,85.8) v1(16.31,33.99) v1(16.38,30.12) v1(16.54,27.31) v1(16.64,22.78) v1(16.61,20.75) v1(16.71,54.94) v1(16.74,53.85) v1(16.69,52.6) v1(16.79,115.8) v1(17.12,60.15) v1(17.12,31.12) v1(17.12,19.74) v1(17.17,70.38) v1(17.17,23.77) v1(17.2,21.84) v1(17.27,62.92) v1(17.3,26.29) v1(17.4,57.63) v1(17.37,28.8) v1(17.42,16.59) v1(17.48,47.9) v1(17.6,105.41) v1(17.7,85.39) v1(17.68,76.73) v1(17.68,75.21) v1(17.68,37.62) v1(17.83,40.41) v1(17.78,35.89) v1(17.81,20.5) v1(17.91,110.79) v1(17.91,95.3) v1(17.93,42.77) v1(18.01,98.2) v1(17.96,34.09) v1(18.03,30.23) v1(18.03,27.43) v1(18.21,58.93) v1(18.29,106.4) v1(18.34,64.21) v1(18.29,61.47) v1(18.26,17.98) v1(18.44,72.16) v1(18.44,70.38) v1(18.64,25.96) v1(18.62,19.71) v1(18.69,36.88) v1(18.8,34.98) v1(18.9,108.2) v1(18.9,82.91) v1(18.95,24.69) v1(18.87,15.85) v1(18.97,32.92) v1(19,31.37) v1(19,28.4) v1(19.13,22.05) v1(19.15,23.29) v1(19.3,85.8) v1(19.3,85.12) v1(19.53,18.8) v1(19.71,76.48) v1(19.71,74.19) v1(19.71,72.16) v1(19.69,64.24) v1(19.74,62.94) v1(19.71,29.97) v1(19.91,27.1) v1(19.96,70.38) v1(19.99,55.63) v1(19.96,37.77) v1(20.07,53.09) v1(20.07,24) v1(20.17,35.97) v1(20.19,32.94) v1(20.29,67.69) v1(20.27,34.24) v1(20.32,25.81) v1(20.4,69.01) v1(20.42,31.42) v1(20.52,16.64) v1(20.65,28.96) v1(20.57,22.76) v1(20.6,17.7) v1(20.7,87.91) v1(20.8,83.41) v1(20.75,36.96) v1(20.93,72.87) v1(20.98,75.21) v1(20.98,70.38) v1(20.98,58.83) v1(21.11,55.55) v1(21.11,53.06) v1(21.21,27.61) v1(21.31,95.1) v1(21.39,64.24) v1(21.39,62.87) v1(21.49,30.33) v1(21.56,24.94) v1(21.62,19.69) v1(21.64,17.68) v1(21.72,32.79) v1(21.74,15.85) v1(21.84,61.29) v1(21.84,35.28) v1(21.89,36.42) v1(22.05,31.47) v1(22.12,58.27) v1(22.12,55.45) v1(22.15,53.19) v1(22.25,72.16) v1(22.25,70.38) v1(22.23,37.54) v1(22.23,26.09) v1(22.3,93.19) v1(22.35,68.63) v1(22.35,27.31) v1(22.5,76.48) v1(22.5,74.45) v1(22.45,20.37) v1(22.58,29.16) v1(22.78,24.92) v1(22.94,38.13) v1(23.01,66.17) v1(22.96,17.7) v1(23.09,111) v1(23.14,85.8) v1(23.14,85.22) v1(23.14,21.31) v1(23.16,19.79) v1(23.27,75.72) v1(23.27,16.61) v1(23.47,28.24) v1(23.57,72.19) v1(23.65,70.41) v1(23.57,63.35) v1(23.6,37.57) v1(23.72,54.99) v1(23.72,29.82) v1(23.8,68.91) v1(23.77,60.68) v1(23.77,58.39) v1(24,22.25) v1(24.05,20.52) v1(24.23,38.15) v1(24.21,27.18) v1(24.31,87.71) v1(24.28,74.19) v1(24.43,16.94) v1(24.41,15.85) v1(24.46,32.92) v1(24.69,116.81) v1(24.69,72.19) v1(24.71,70.43) v1(24.71,28.6) v1(24.74,17.7) v1(24.79,67.59) v1(24.84,19.79) v1(24.94,23.16) v1(25.1,89.92) v1(25.1,83.59) v1(25.3,76.73) v1(25.27,26.82) v1(25.27,21.77) v1(25.5,87.3) v1(25.53,45.77) v1(25.48,44.6) v1(25.6,75.39) v1(25.65,20.27) v1(25.93,24.13) v1(26.09,46.96) v1(26.21,67.77) v1(26.21,64.59) v1(26.16,62.87) v1(26.21,60.63) v1(26.24,58.85) v1(26.31,72.16) v1(26.31,70.38) v1(26.29,57.71) v1(26.34,55.65) v1(26.31,53.09) v1(26.29,48.64) v1(26.34,32.44) v1(26.34,29.26) v1(26.34,19.53) v1(26.44,83.69) v1(26.59,22.99) v1(26.62,21.06) v1(26.67,18.8) v1(26.7,17.81) v1(26.7,16.84) v1(26.8,15.85) v1(26.87,30.94) v1(26.92,24.28) v1(27.03,33.1) v1(27.2,85.73) v1(27.25,85.22) v1(27.43,74.24) v1(27.38,31.52) v1(27.51,88.21) v1(27.48,28.88) v1(27.69,19.28) v1(27.71,15.19) v1(27.84,72.16) v1(27.84,70.38) v1(27.81,61.37) v1(27.76,58.9) v1(27.81,56.29) v1(27.76,53.72) v1(27.94,48.67) v1(27.91,17.3) v1(28.04,63.27) v1(28.09,76.15) v1(28.07,67.69) v1(28.12,65.58) v1(28.09,22.68) v1(28.19,47.6) v1(28.24,24.03) v1(28.35,86.79) v1(28.32,52.63) v1(28.27,20.5) v1(28.37,57.76) v1(28.52,55.27) v1(28.83,18.82) v1(28.96,16.38) v1(29.08,60.12) v1(29.31,48.74) v1(29.31,21.51) v1(29.41,65.18) v1(29.41,23.11) v1(29.57,58.55) v1(29.57,53.42) v1(29.57,27.13) v1(29.74,56.24) v1(29.69,19.94) v1(29.79,83.9) v1(29.85,17.42) v1(29.87,70.51) v1(29.92,24.36) v1(29.87,15.21) v1(30.05,26.09) v1(30.1,72.09) v1(30.2,87.6) v1(30.33,63.83) v1(30.4,66.27) v1(30.43,61.44) v1(30.38,27.23) v1(30.53,76.1) v1(30.51,74.32) v1(30.48,69.34) v1(30.51,55.09) v1(30.58,21.26) v1(30.63,16.36) v1(30.68,18.9) v1(30.84,73.05) v1(31.01,52.63) v1(31.09,22.45) v1(31.29,70.48) v1(31.47,58.27) v1(31.52,56.16) v1(31.47,17.4) v1(31.65,53.75) v1(31.65,48.64) v1(31.57,23.88) v1(31.62,20.12) v1(31.6,15.21) v1(32.11,60.1) v1(32.13,31.9) v1(32.21,116.1) v1(32.18,69.42) v1(32.16,65.28) v1(32.18,28.6) v1(32.31,62.79) v1(32.33,22.86) v1(32.28,18.69) v1(32.31,16.38) v1(32.51,21.46) v1(32.56,24.41) v1(32.84,72.11) v1(32.84,57.2) v1(32.94,74.4) v1(32.87,70.41) v1(32.94,61.44) v1(32.99,84.81) v1(32.97,75.67) v1(33.02,55.37) v1(32.99,53.21) v1(33.07,58.9) v1(33.15,29.84) v1(33.15,19.99) v1(33.2,63.83) v1(33.22,30.86) v1(33.22,15.21) v1(33.27,17.45) v1(33.48,24.05) v1(33.76,69.42) v1(33.78,65.23) v1(33.83,27.15) v1(33.88,28.19) v1(33.93,18.82) v1(34.01,21.69) v1(34.09,83.29) v1(34.06,16.33) v1(34.24,72.14) v1(34.34,66.27) v1(34.39,70.41) v1(34.37,61.39) v1(34.47,20.09) v1(34.75,29.9) v1(34.75,26.64) v1(34.8,62.69) v1(34.85,27.66) v1(34.9,58.98) v1(34.9,15.21) v1(35,60.15) v1(35,22.15) v1(34.98,17.37) v1(35.13,25.07) v1(35.43,20.27) v1(35.53,18.75) v1(35.61,87.6) v1(35.56,26.26) v1(35.69,27.64) v1(35.71,21.44) v1(35.81,16.33) v1(35.97,23.75) v1(36.07,26.92) v1(36.32,25.07) v1(36.35,20.7) v1(36.4,75.13) v1(36.45,27.69) v1(36.45,26.11) v1(36.53,53.21) v1(36.55,55.32) v1(36.63,17.37) v1(36.65,15.27) v1(36.75,18.75) v1(37.06,20.02) v1(37.21,27.71) v1(37.21,24.18) v1(37.31,26.92) v1(37.29,25.96) v1(37.49,72.03) v1(37.54,25.02) v1(37.72,16.43) v1(37.8,87.5) v1(37.85,22.91) v1(37.8,21.82) v1(37.8,19.23) v1(37.77,18.26) v1(37.97,27.94) v1(38.18,41.94) v1(38.25,70.38) v1(38.4,25.55) v1(38.51,41.15) v1(38.48,31.17) v1(38.48,24.33) v1(38.56,68.83) v1(38.58,21.03) v1(38.81,28.6) v1(38.79,18.26) v1(38.81,16.92) v1(38.99,26.72) v1(39.12,30.38) v1(39.22,78.94) v1(39.27,81.15) v1(39.32,29.36) v1(39.32,27.76) v1(39.4,89.92) v1(39.42,23.16) v1(39.4,21.67) v1(39.42,20.17) v1(39.5,83.41) v1(39.5,25.22) v1(39.55,24.43) v1(39.6,86.11) v1(39.65,77.55) v1(39.6,66.19) v1(39.83,25.88) v1(39.8,17.2) v1(39.8,15.9) v1(39.93,52.6) v1(40.03,70.38) v1(40.03,55.52) v1(40.11,75.79) v1(40.06,60.2) v1(40.08,59) v1(40.08,57.38) v1(40.08,53.82) v1(40.13,30.2) v1(40.41,67.72) v1(40.39,31.19) v1(40.36,28.5) v1(40.36,26.77) v1(40.51,69.22) v1(40.51,64.11) v1(40.56,62.74) v1(40.89,29.21) v1(41.05,18.67) v1(41.07,27.71) v1(41.25,25.96) v1(41.25,23.6) v1(41.25,22.2) v1(41.25,19.51) v1(41.3,70.38) v1(41.28,20.96) v1(41.45,29.97) v1(41.61,80.11) v1(41.63,49.38) v1(41.71,17.45) v1(41.73,16.05) v1(41.71,15.21) v1(41.83,62.64) v1(41.83,61.52) v1(41.76,28.57) v1(41.76,26.82) v1(41.86,60.15) v1(41.86,44.4) v1(41.99,64.41) v1(42.04,31.17) v1(42.09,75.11) v1(42.32,25.96) v1(42.32,23.6) v1(42.32,21.29) v1(42.44,27.74) v1(42.44,19.46) v1(42.47,29.31) v1(42.52,18.59) v1(42.9,26.82) v1(43.03,22.33) v1(43.1,75.21) v1(43.13,57.53) v1(43.08,56.34) v1(43.05,15.21) v1(43.21,20.35) v1(43.23,17.63) v1(43.31,28.57) v1(43.43,30.05) v1(43.48,59.56) v1(43.51,25.96) v1(43.51,23.6) v1(43.59,62.13) v1(43.59,32.38) v1(43.56,31.01) v1(43.79,21.31) v1(43.87,27.91) v1(43.94,18.75) v1(43.97,49.4) v1(44.04,29.31) v1(44.09,55.02) v1(44.15,26.7) v1(44.09,16.46) v1(44.22,19.99) v1(44.32,35.31) v1(44.42,57.66) v1(44.42,40.54) v1(44.4,33.93) v1(44.5,89.92) v1(44.53,66.37) v1(44.5,54) v1(44.6,62.79) v1(44.6,61.52) v1(44.55,60.12) v1(44.58,59.06) v1(44.58,52.6) v1(44.7,56.41) v1(44.68,31.78) v1(44.83,28.65) v1(44.78,15.21) v1(44.86,27.31) v1(44.88,25.98) v1(44.91,23.57) v1(44.86,22.22) v1(44.88,20.75) v1(45.01,67.51) v1(45.09,34.65) v1(45.09,32.79) v1(45.11,18.75) v1(45.31,17.6) v1(45.36,70.38) v1(45.36,64.41) v1(45.49,35.61) v1(45.59,117.2) v1(45.64,33.93) v1(45.8,75.01) v1(45.92,20.45) v1(46,55.07) v1(46.05,19.48) v1(46.1,84.81) v1(46.18,29.08) v1(46.28,56.85) v1(46.28,16.51) v1(46.63,15.21) v1(46.84,69.01) v1(46.89,72.16) v1(47.14,70.38) v1(47.24,64.01) v1(47.19,61.52) v1(47.19,60.17) v1(47.22,58.93) v1(47.29,67.08) v1(47.27,62.71) v1(47.42,76.38) v1(47.4,17.65) v1(47.52,74.47) v1(47.9,72.16) v1(48.01,77.9) v1(48.29,16.43) v1(48.51,15.21) v1(48.59,43.41) v1(48.92,76.73) v1(48.92,75.21) v1(48.92,73.69) v1(48.97,72.21) v1(49.02,17.58) v1(49.23,42.39) v1(50.09,16.48) v1(50.7,76.73) v1(50.7,75.21) v1(50.7,73.43) v1(50.7,72.16) v1(50.88,42.88) v1(50.93,15.21) v1(51,113.89) v1(51,88.6) v1(50.95,17.53) v1(51.23,29.11) v1(51.26,20.47) v1(51.26,19.48) v1(51.71,72.16) v1(51.79,74.35) v1(52.22,77.24) v1(52.73,72.16) v1(52.81,75.79) v1(52.91,73.28) v1(53.29,74.6) v1(53.62,15.21) v1(53.7,38.3) v1(53.8,42.9) v1(54.1,69.8) v1(54.31,77.9) v1(54.31,67.13) v1(54.28,65.05) v1(54.25,62.33) v1(54.28,59.74) v1(54.25,57.23) v1(54.28,54.94) v1(54.28,52.04) v1(54.36,49.5) v1(54.43,46.86) v1(55.6,37.01) v1(55.68,15.21) v1(56.26,45.03) v1(56.39,79.71) v1(56.9,107.7) v1(56.9,65.94) v1(56.95,63.5) v1(56.95,61.01) v1(56.95,58.17) v1(56.95,55.93) v1(56.95,53.47) v1(56.92,50.75) v1(57,95.91) v1(57,47.98) v1(57.12,46.2) v1(57.61,69.49) v1(57.61,38.3) v1(57.73,15.21) v4(13.21,110.01) v4(13.21,109.09) v4(13.21,108.2) v4(30.3,40.51) v4(30.3,39.5) v4(30.3,38.51) v4(30.3,37.52) v4(30.3,36.5) v4(31.29,40.51) v4(31.29,39.5) v4(31.29,38.51) v4(31.29,37.52) v4(31.29,36.5) v4(32.31,40.51) v4(32.31,39.5) v4(32.31,38.51) v4(32.31,37.52) v4(32.31,36.5) v4(33.3,40.51) v4(33.3,39.5) v4(33.3,38.51) v4(33.3,37.52) v4(33.3,36.5) v4(34.29,40.51) v4(34.29,39.5) v4(34.29,38.51) v4(34.29,37.52) v4(34.29,36.5)
